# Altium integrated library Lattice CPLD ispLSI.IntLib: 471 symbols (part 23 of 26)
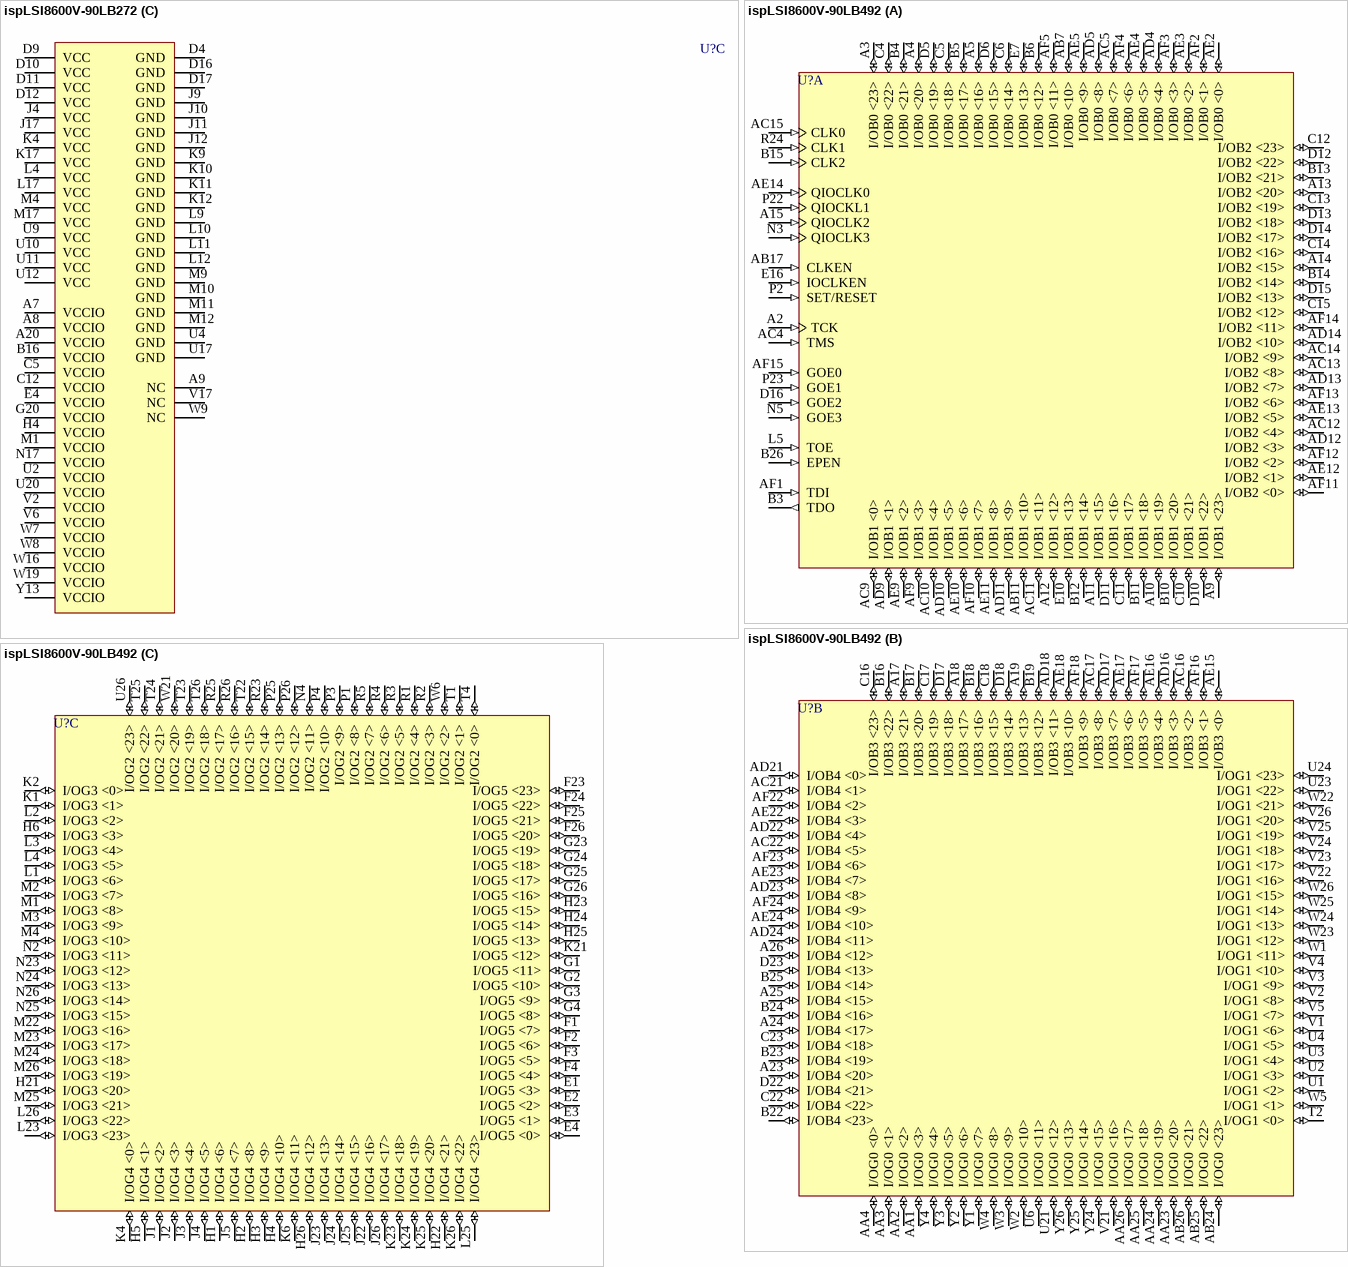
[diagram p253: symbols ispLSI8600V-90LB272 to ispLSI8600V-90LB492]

## ispLSI8600V-90LB272
designator U?
3.3V In-System Programmable SuperBIG High Density PLD
footprint BGA272 (BGA, 272-Leads, Body 27x27mm, Pitch 1.27mm)
3D model 8600V-BGA272 (272-Ball Ball Grid Array (BGA272))
part A pins: A4 TCK (in), A5 I/OB0 <21> (io), A6 I/OB0 <18> (io), A10 I/OB3 <22> (io), A11 I/OB3 <19> (io), A12 I/OB3 <16> (io), A13 I/OB3 <15> (io), A14 I/OB4 <22> (io), A15 I/OB4 <21> (io), A16 I/OB4 <17> (io), A17 I/OB4 <13> (io), B4 I/OB0 <23> (io), B5 I/OB0 <20> (io), B6 I/OB0 <16> (io), B7 I/OB0 <15> (io), B8 I/OB0 <12> (io), B9 IOCLKEN (in), B10 I/OB3 <21> (io), B11 I/OB3 <18> (io), B12 I/OB3 <17> (io), B13 I/OB3 <14> (io), B14 I/OB3 <12> (io), B15 I/OB4 <18> (io), B17 I/OB4 <12> (io), C4 TDO (out), C6 I/OB0 <17> (io), C7 I/OB0 <13> (io), C8 QIOCLK2 (in), C9 GOE2 (in), C10 I/OB3 <23> (io), C11 I/OB3 <20> (io), C13 I/OB4 <23> (io), C14 I/OB4 <20> (io), C15 I/OB4 <16> (io), C16 I/OB4 <14> (io), C17 EPEN (in), D5 I/OB0 <22> (io), D6 I/OB0 <19> (io), D7 I/OB0 <14> (io), D8 CLK2 (in), D13 I/OB3 <13> (io), D14 I/OB4 <19> (io), D15 I/OB4 <15> (io), L3 TOE (in), M19 GOE1 (in), M20 QIOCLK1 (in), N1 GOE3 (in), N2 QIOCLK3 (in), P3 SET/RESET (in), P18 CLK1 (in), R4 I/OG0 <10> (io), R17 I/OG0 <13> (io), T4 I/OG0 <11> (io), T17 I/OG0 <18> (io), U3 I/OG0 <9> (io), U5 TDI (in), U6 I/OB0 <4> (io), U7 I/OB0 <5> (io), U8 I/OB0 <10> (io), U13 I/OB3 <9> (io), U14 I/OB4 <2> (io), U15 I/OB4 <6> (io), U16 I/OB4 <9> (io), U18 I/OG0 <16> (io), U19 I/OG0 <12> (io), V1 I/OG0 <8> (io), V3 I/OG0 <7> (io), V4 I/OG0 <0> (io), V5 I/OB0 <1> (io), V7 I/OB0 <7> (io), V8 I/OB0 <11> (io), V9 CLKEN (in), V10 I/OB3 <0> (io), V11 I/OB3 <4> (io), V12 I/OB3 <7> (io), V13 I/OB3 <10> (io), V14 I/OB4 <1> (io), V15 I/OB4 <5> (io), V16 I/OB4 <8> (io), V18 I/OG0 <17> (io), V19 I/OG0 <15> (io), V20 I/OG0 <14> (io), W1 I/OG0 <6> (io), W2 I/OG0 <5> (io), W3 I/OG0 <3> (io), W4 TMS (in), W5 I/OB0 <2> (io), W6 I/OB0 <6> (io), W10 I/OB3 <1> (io), W11 I/OB3 <3> (io), W12 I/OB3 <6> (io), W13 I/OB3 <8> (io), W14 I/OB4 <0> (io), W15 I/OB4 <4> (io), W17 I/OB4 <10> (io), W18 I/OG0 <22> (io), W20 I/OG0 <19> (io), Y1 I/OG0 <4> (io), Y2 I/OG0 <2> (io), Y3 I/OG0 <1> (io), Y4 I/OB0 <0> (io), Y5 I/OB0 <3> (io), Y6 I/OB0 <8> (io), Y7 I/OB0 <9> (io), Y8 QIOCLK0 (in), Y9 CLK0 (in), Y10 GOE0 (in), Y11 I/OB3 <2> (io), Y12 I/OB3 <5> (io), Y14 I/OB3 <11> (io), Y15 I/OB4 <3> (io), Y16 I/OB4 <7> (io), Y17 I/OB4 <11> (io), Y18 I/OG0 <23> (io), Y19 I/OG0 <21> (io), Y20 I/OG0 <20> (io)
part B pins: A1 I/OG5 <4> (io), A2 I/OG5 <3> (io), A3 I/OG5 <0> (io), A18 I/OG5 <23> (io), A19 I/OG5 <16> (io), B1 I/OG5 <5> (io), B2 I/OG5 <1> (io), B3 I/OG5 <2> (io), B18 I/OG5 <22> (io), B19 I/OG5 <19> (io), B20 I/OG5 <15> (io), C1 I/OG5 <11> (io), C2 I/OG5 <9> (io), C3 I/OG5 <8> (io), C18 I/OG5 <20> (io), C19 I/OG5 <17> (io), C20 I/OG5 <14> (io), D1 I/OG5 <10> (io), D2 I/OG5 <7> (io), D3 I/OG5 <6> (io), D18 I/OG5 <18> (io), D19 I/OG5 <12> (io), D20 I/OG4 <12> (io), E1 I/OG4 <9> (io), E2 I/OG4 <10> (io), E3 I/OG4 <11> (io), E17 I/OG5 <21> (io), E18 I/OG5 <13> (io), E19 I/OG4 <14> (io), E20 I/OG4 <18> (io), F1 I/OG4 <6> (io), F2 I/OG4 <7> (io), F3 I/OG4 <5> (io), F4 I/OG4 <8> (io), F17 I/OG4 <13> (io), F18 I/OG4 <17> (io), F19 I/OG4 <19> (io), F20 I/OG4 <21> (io), G1 I/OG4 <1> (io), G2 I/OG4 <0> (io), G3 I/OG4 <3> (io), G4 I/OG4 <4> (io), G17 I/OG4 <15> (io), G18 I/OG4 <16> (io), G19 I/OG4 <23> (io), H1 I/OG3 <1> (io), H2 I/OG3 <0> (io), H3 I/OG4 <2> (io), H17 I/OG4 <20> (io), H18 I/OG4 <22> (io), H19 I/OG3 <22> (io), H20 I/OG3 <20> (io), J1 I/OG3 <4> (io), J2 I/OG3 <3> (io), J3 I/OG3 <2> (io), J18 I/OG3 <23> (io), J19 I/OG3 <21> (io), J20 I/OG3 <19> (io), K1 I/OG3 <7> (io), K2 I/OG3 <6> (io), K3 I/OG3 <5> (io), K18 I/OG3 <18> (io), K19 I/OG3 <17> (io), K20 I/OG3 <16> (io), L1 I/OG3 <9> (io), L2 I/OG3 <8> (io), L18 I/OG3 <15> (io), L19 I/OG3 <14> (io), L20 I/OG3 <13> (io), M2 I/OG3 <10> (io), M3 I/OG3 <11> (io), M18 I/OG3 <12> (io), N3 I/OG2 <10> (io), N4 I/OG2 <9> (io), N18 I/OG2 <12> (io), N19 I/OG2 <13> (io), N20 I/OG2 <14> (io), P1 I/OG2 <11> (io), P2 I/OG2 <8> (io), P4 I/OG2 <7> (io), P17 I/OG2 <16> (io), P19 I/OG2 <15> (io), P20 I/OG2 <17> (io), R1 I/OG2 <6> (io), R2 I/OG2 <5> (io), R3 I/OG2 <4> (io), R18 I/OG2 <20> (io), R19 I/OG2 <19> (io), R20 I/OG2 <18> (io), T1 I/OG2 <3> (io), T2 I/OG2 <2> (io), T3 I/OG2 <1> (io), T18 I/OG2 <23> (io), T19 I/OG2 <22> (io), T20 I/OG2 <21> (io), U1 I/OG2 <0> (io)
part C pins: A7 VCCIO (power), A8 VCCIO (power), A9 NC, A20 VCCIO (power), B16 VCCIO (power), C5 VCCIO (power), C12 VCCIO (power), D4 GND (power), D9 VCC (power), D10 VCC (power), D11 VCC (power), D12 VCC (power), D16 GND (power), D17 GND (power), E4 VCCIO (power), G20 VCCIO (power), H4 VCCIO (power), J4 VCC (power), J9 GND (power), J10 GND (power), J11 GND (power), J12 GND (power), J17 VCC (power), K4 VCC (power), K9 GND (power), K10 GND (power), K11 GND (power), K12 GND (power), K17 VCC (power), L4 VCC (power), L9 GND (power), L10 GND (power), L11 GND (power), L12 GND (power), L17 VCC (power), M1 VCCIO (power), M4 VCC (power), M9 GND (power), M10 GND (power), M11 GND (power), M12 GND (power), M17 VCC (power), N17 VCCIO (power), U2 VCCIO (power), U4 GND (power), U9 VCC (power), U10 VCC (power), U11 VCC (power), U12 VCC (power), U17 GND (power), U20 VCCIO (power), V2 VCCIO (power), V6 VCCIO (power), V17 NC, W7 VCCIO (power), W8 VCCIO (power), W9 NC, W16 VCCIO (power), W19 VCCIO (power), Y13 VCCIO (power)

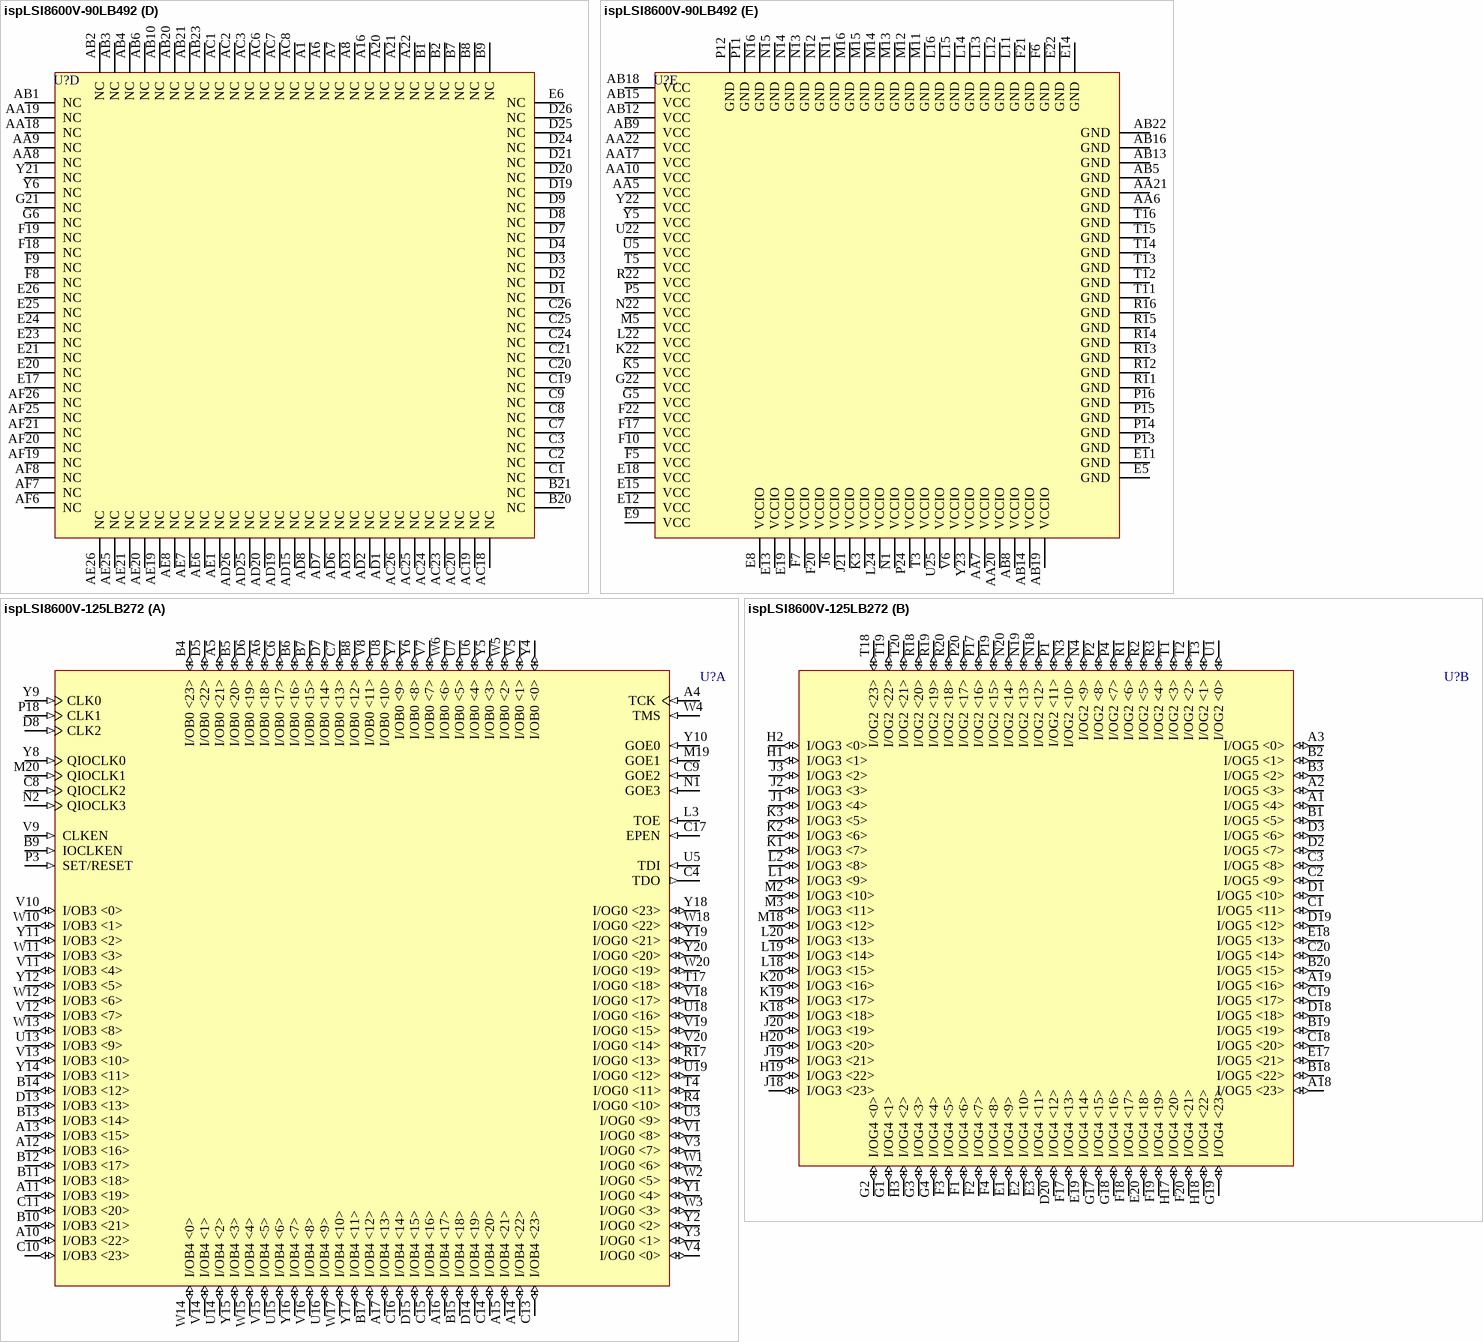
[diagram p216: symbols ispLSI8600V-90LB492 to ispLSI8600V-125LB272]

## ispLSI8600V-90LB492
designator U?
3.3V In-System Programmable SuperBIG High Density PLD
footprint BGA492 (BGA, 492-Leads, Body 35x35mm, Pitch 1.27mm)
3D model 8600V-BGA492 (492-Ball Ball Grid Array (BGA492))
part A pins: A2 TCK (in), A3 I/OB0 <23> (io), A4 I/OB0 <20> (io), A5 I/OB0 <16> (io), A9 I/OB1 <23> (io), A10 I/OB1 <19> (io), A11 I/OB1 <15> (io), A12 I/OB1 <12> (io), A13 I/OB2 <20> (io), A14 I/OB2 <15> (io), A15 QIOCLK2 (in), AB7 I/OB0 <10> (io), AB11 I/OB1 <10> (io), AB17 CLKEN (in), AC4 TMS (in), AC5 I/OB0 <7> (io), AC9 I/OB1 <0> (io), AC10 I/OB1 <4> (io), AC11 I/OB1 <11> (io), AC12 I/OB2 <4> (io), AC13 I/OB2 <8> (io), AC14 I/OB2 <9> (io), AC15 CLK0 (in), AD4 I/OB0 <4> (io), AD5 I/OB0 <8> (io), AD9 I/OB1 <1> (io), AD10 I/OB1 <5> (io), AD11 I/OB1 <9> (io), AD12 I/OB2 <3> (io), AD13 I/OB2 <7> (io), AD14 I/OB2 <10> (io), AE2 I/OB0 <0> (io), AE3 I/OB0 <2> (io), AE4 I/OB0 <5> (io), AE5 I/OB0 <9> (io), AE9 I/OB1 <2> (io), AE10 I/OB1 <6> (io), AE11 I/OB1 <8> (io), AE12 I/OB2 <1> (io), AE13 I/OB2 <5> (io), AE14 QIOCLK0 (in), AF1 TDI (in), AF2 I/OB0 <1> (io), AF3 I/OB0 <3> (io), AF4 I/OB0 <6> (io), AF5 I/OB0 <11> (io), AF9 I/OB1 <3> (io), AF10 I/OB1 <7> (io), AF11 I/OB2 <0> (io), AF12 I/OB2 <2> (io), AF13 I/OB2 <6> (io), AF14 I/OB2 <11> (io), AF15 GOE0 (in), B3 TDO (out), B4 I/OB0 <21> (io), B5 I/OB0 <17> (io), B6 I/OB0 <12> (io), B10 I/OB1 <20> (io), B11 I/OB1 <18> (io), B12 I/OB1 <14> (io), B13 I/OB2 <21> (io), B14 I/OB2 <14> (io), B15 CLK2 (in), B26 EPEN (in), C4 I/OB0 <22> (io), C5 I/OB0 <18> (io), C6 I/OB0 <14> (io), C10 I/OB1 <21> (io), C11 I/OB1 <17> (io), C12 I/OB2 <23> (io), C13 I/OB2 <19> (io), C14 I/OB2 <16> (io), C15 I/OB2 <12> (io), D5 I/OB0 <19> (io), D6 I/OB0 <15> (io), D10 I/OB1 <22> (io), D11 I/OB1 <16> (io), D12 I/OB2 <22> (io), D13 I/OB2 <18> (io), D14 I/OB2 <17> (io), D15 I/OB2 <13> (io), D16 GOE2 (in), E7 I/OB0 <13> (io), E10 I/OB1 <13> (io), E16 IOCLKEN (in), L5 TOE (in), N3 QIOCLK3 (in), N5 GOE3 (in), P2 SET/RESET (in), P22 QIOCKL1 (in), P23 GOE1 (in), R24 CLK1 (in)
part B pins: A17 I/OB3 <21> (io), A18 I/OB3 <17> (io), A19 I/OB3 <13> (io), A23 I/OB4 <20> (io), A24 I/OB4 <17> (io), A25 I/OB4 <15> (io), A26 I/OB4 <12> (io), AA1 I/OG0 <3> (io), AA2 I/OG0 <2> (io), AA3 I/OG0 <1> (io), AA4 I/OG0 <0> (io), AA23 I/OG0 <20> (io), AA24 I/OG0 <19> (io), AA25 I/OG0 <18> (io), AA26 I/OG0 <17> (io), AB24 I/OG0 <23> (io), AB25 I/OG0 <22> (io), AB26 I/OG0 <21> (io), AC16 I/OB3 <2> (io), AC17 I/OB3 <8> (io), AC21 I/OB4 <1> (io), AC22 I/OB4 <5> (io), AD16 I/OB3 <3> (io), AD17 I/OB3 <7> (io), AD18 I/OB3 <11> (io), AD21 I/OB4 <0> (io), AD22 I/OB4 <4> (io), AD23 I/OB4 <8> (io), AD24 I/OB4 <11> (io), AE15 I/OB3 <0> (io), AE16 I/OB3 <4> (io), AE17 I/OB3 <6> (io), AE18 I/OB3 <10> (io), AE22 I/OB4 <3> (io), AE23 I/OB4 <7> (io), AE24 I/OB4 <10> (io), AF16 I/OB3 <1> (io), AF17 I/OB3 <5> (io), AF18 I/OB3 <9> (io), AF22 I/OB4 <2> (io), AF23 I/OB4 <6> (io), AF24 I/OB4 <9> (io), B16 I/OB3 <22> (io), B17 I/OB3 <20> (io), B18 I/OB3 <16> (io), B19 I/OB3 <12> (io), B22 I/OB4 <23> (io), B23 I/OB4 <19> (io), B24 I/OB4 <16> (io), B25 I/OB4 <14> (io), C16 I/OB3 <23> (io), C17 I/OB3 <19> (io), C18 I/OB3 <15> (io), C22 I/OB4 <22> (io), C23 I/OB4 <18> (io), D17 I/OB3 <18> (io), D18 I/OB3 <14> (io), D22 I/OB4 <21> (io), D23 I/OB4 <13> (io), T2 I/OG1 <0> (io), U1 I/OG1 <2> (io), U2 I/OG1 <3> (io), U3 I/OG1 <4> (io), U4 I/OG1 <5> (io), U6 I/OG0 <11> (io), U21 I/OG0 <12> (io), U23 I/OG1 <22> (io), U24 I/OG1 <23> (io), V1 I/OG1 <6> (io), V2 I/OG1 <8> (io), V3 I/OG1 <9> (io), V4 I/OG1 <10> (io), V5 I/OG1 <7> (io), V21 I/OG0 <16> (io), V22 I/OG1 <16> (io), V23 I/OG1 <17> (io), V24 I/OG1 <18> (io), V25 I/OG1 <19> (io), V26 I/OG1 <20> (io), W1 I/OG1 <11> (io), W2 I/OG0 <10> (io), W3 I/OG0 <9> (io), W4 I/OG0 <8> (io), W5 I/OG1 <1> (io), W22 I/OG1 <21> (io), W23 I/OG1 <12> (io), W24 I/OG1 <13> (io), W25 I/OG1 <14> (io), W26 I/OG1 <15> (io), Y1 I/OG0 <7> (io), Y2 I/OG0 <6> (io), Y3 I/OG0 <5> (io), Y4 I/OG0 <4> (io), Y24 I/OG0 <15> (io), Y25 I/OG0 <14> (io), Y26 I/OG0 <13> (io)
part C pins: E1 I/OG5 <3> (io), E2 I/OG5 <2> (io), E3 I/OG5 <1> (io), E4 I/OG5 <0> (io), F1 I/OG5 <7> (io), F2 I/OG5 <6> (io), F3 I/OG5 <5> (io), F4 I/OG5 <4> (io), F23 I/OG5 <23> (io), F24 I/OG5 <22> (io), F25 I/OG5 <21> (io), F26 I/OG5 <20> (io), G1 I/OG5 <11> (io), G2 I/OG5 <10> (io), G3 I/OG5 <9> (io), G4 I/OG5 <8> (io), G23 I/OG5 <19> (io), G24 I/OG5 <18> (io), G25 I/OG5 <17> (io), G26 I/OG5 <16> (io), H1 I/OG4 <6> (io), H2 I/OG4 <8> (io), H3 I/OG4 <9> (io), H4 I/OG4 <10> (io), H5 I/OG4 <1> (io), H6 I/OG3 <3> (io), H21 I/OG3 <20> (io), H22 I/OG4 <21> (io), H23 I/OG5 <15> (io), H24 I/OG5 <14> (io), H25 I/OG5 <13> (io), H26 I/OG4 <12> (io), J1 I/OG4 <2> (io), J2 I/OG4 <3> (io), J3 I/OG4 <4> (io), J4 I/OG4 <5> (io), J5 I/OG4 <7> (io), J22 I/OG4 <16> (io), J23 I/OG4 <13> (io), J24 I/OG4 <14> (io), J25 I/OG4 <15> (io), J26 I/OG4 <17> (io), K1 I/OG3 <1> (io), K2 I/OG3 <0> (io), K4 I/OG4 <0> (io), K6 I/OG4 <11> (io), K21 I/OG5 <12> (io), K23 I/OG4 <18> (io), K24 I/OG4 <19> (io), K25 I/OG4 <20> (io), K26 I/OG4 <22> (io), L1 I/OG3 <6> (io), L2 I/OG3 <2> (io), L3 I/OG3 <4> (io), L4 I/OG3 <5> (io), L23 I/OG3 <23> (io), L25 I/OG4 <23> (io), L26 I/OG3 <22> (io), M1 I/OG3 <8> (io), M2 I/OG3 <7> (io), M3 I/OG3 <9> (io), M4 I/OG3 <10> (io), M22 I/OG3 <16> (io), M23 I/OG3 <17> (io), M24 I/OG3 <18> (io), M25 I/OG3 <21> (io), M26 I/OG3 <19> (io), N2 I/OG3 <11> (io), N4 I/OG2 <11> (io), N23 I/OG3 <12> (io), N24 I/OG3 <13> (io), N25 I/OG3 <15> (io), N26 I/OG3 <14> (io), P1 I/OG2 <8> (io), P3 I/OG2 <9> (io), P4 I/OG2 <10> (io), P25 I/OG2 <13> (io), P26 I/OG2 <12> (io), R1 I/OG2 <4> (io), R2 I/OG2 <3> (io), R3 I/OG2 <5> (io), R4 I/OG2 <6> (io), R5 I/OG2 <7> (io), R23 I/OG2 <14> (io), R25 I/OG2 <17> (io), R26 I/OG2 <16> (io), T1 I/OG2 <1> (io), T4 I/OG2 <0> (io), T22 I/OG2 <15> (io), T23 I/OG2 <19> (io), T24 I/OG2 <21> (io), T25 I/OG2 <22> (io), T26 I/OG2 <18> (io), U26 I/OG2 <23> (io), W6 I/OG2 <2> (io), W21 I/OG2 <20> (io)
part D pins: A1 NC, A6 NC, A7 NC, A8 NC, A16 NC, A20 NC, A21 NC, A22 NC, AA8 NC, AA9 NC, AA18 NC, AA19 NC, AB1 NC, AB2 NC, AB3 NC, AB4 NC, AB6 NC, AB10 NC, AB20 NC, AB21 NC, AB23 NC, AC1 NC, AC2 NC, AC3 NC, AC6 NC, AC7 NC, AC8 NC, AC18 NC, AC19 NC, AC20 NC, AC23 NC, AC24 NC, AC25 NC, AC26 NC, AD1 NC, AD2 NC, AD3 NC, AD6 NC, AD7 NC, AD8 NC, AD15 NC, AD19 NC, AD20 NC, AD25 NC, AD26 NC, AE1 NC, AE6 NC, AE7 NC, AE8 NC, AE19 NC, AE20 NC, AE21 NC, AE25 NC, AE26 NC, AF6 NC, AF7 NC, AF8 NC, AF19 NC, AF20 NC, AF21 NC, AF25 NC, AF26 NC, B1 NC, B2 NC, B7 NC, B8 NC, B9 NC, B20 NC, B21 NC, C1 NC, C2 NC, C3 NC, C7 NC, C8 NC, C9 NC, C19 NC, C20 NC, C21 NC, C24 NC, C25 NC, C26 NC, D1 NC, D2 NC, D3 NC, D4 NC, D7 NC, D8 NC, D9 NC, D19 NC, D20 NC, D21 NC, D24 NC, D25 NC, D26 NC, E6 NC, E17 NC, E20 NC, E21 NC, E23 NC, E24 NC, E25 NC, E26 NC, F8 NC, F9 NC, F18 NC, F19 NC, G6 NC, G21 NC, Y6 NC, Y21 NC
part E pins: AA5 VCC (power), AA6 GND (power), AA7 VCCIO (power), AA10 VCC (power), AA17 VCC (power), AA20 VCCIO (power), AA21 GND (power), AA22 VCC (power), AB5 GND (power), AB8 VCCIO (power), AB9 VCC (power), AB12 VCC (power), AB13 GND (power), AB14 VCCIO (power), AB15 VCC (power), AB16 GND (power), AB18 VCC (power), AB19 VCCIO (power), AB22 GND (power), E5 GND (power), E8 VCCIO (power), E9 VCC (power), E11 GND (power), E12 VCC (power), E13 VCCIO (power), E14 GND (power), E15 VCC (power), E18 VCC (power), E19 VCCIO (power), E22 GND (power), F5 VCC (power), F6 GND (power), F7 VCCIO (power), F10 VCC (power), F17 VCC (power), F20 VCCIO (power), F21 GND (power), F22 VCC (power), G5 VCC (power), G22 VCC (power), J6 VCCIO (power), J21 VCCIO (power), K3 VCCIO (power), K5 VCC (power), K22 VCC (power), L11 GND (power), L12 GND (power), L13 GND (power), L14 GND (power), L15 GND (power), L16 GND (power), L22 VCC (power), L24 VCCIO (power), M5 VCC (power), M11 GND (power), M12 GND (power), M13 GND (power), M14 GND (power), M15 GND (power), M16 GND (power), N1 VCCIO (power), N11 GND (power), N12 GND (power), N13 GND (power), N14 GND (power), N15 GND (power), N16 GND (power), N22 VCC (power), P5 VCC (power), P11 GND (power), P12 GND (power), P13 GND (power), P14 GND (power), P15 GND (power), P16 GND (power), P24 VCCIO (power), R11 GND (power), R12 GND (power), R13 GND (power), R14 GND (power), R15 GND (power), R16 GND (power), R22 VCC (power), T3 VCCIO (power), T5 VCC (power), T11 GND (power), T12 GND (power), T13 GND (power), T14 GND (power), T15 GND (power), T16 GND (power), U5 VCC (power), U22 VCC (power), U25 VCCIO (power), V6 VCCIO (power), Y5 VCC (power), Y22 VCC (power), Y23 VCCIO (power)

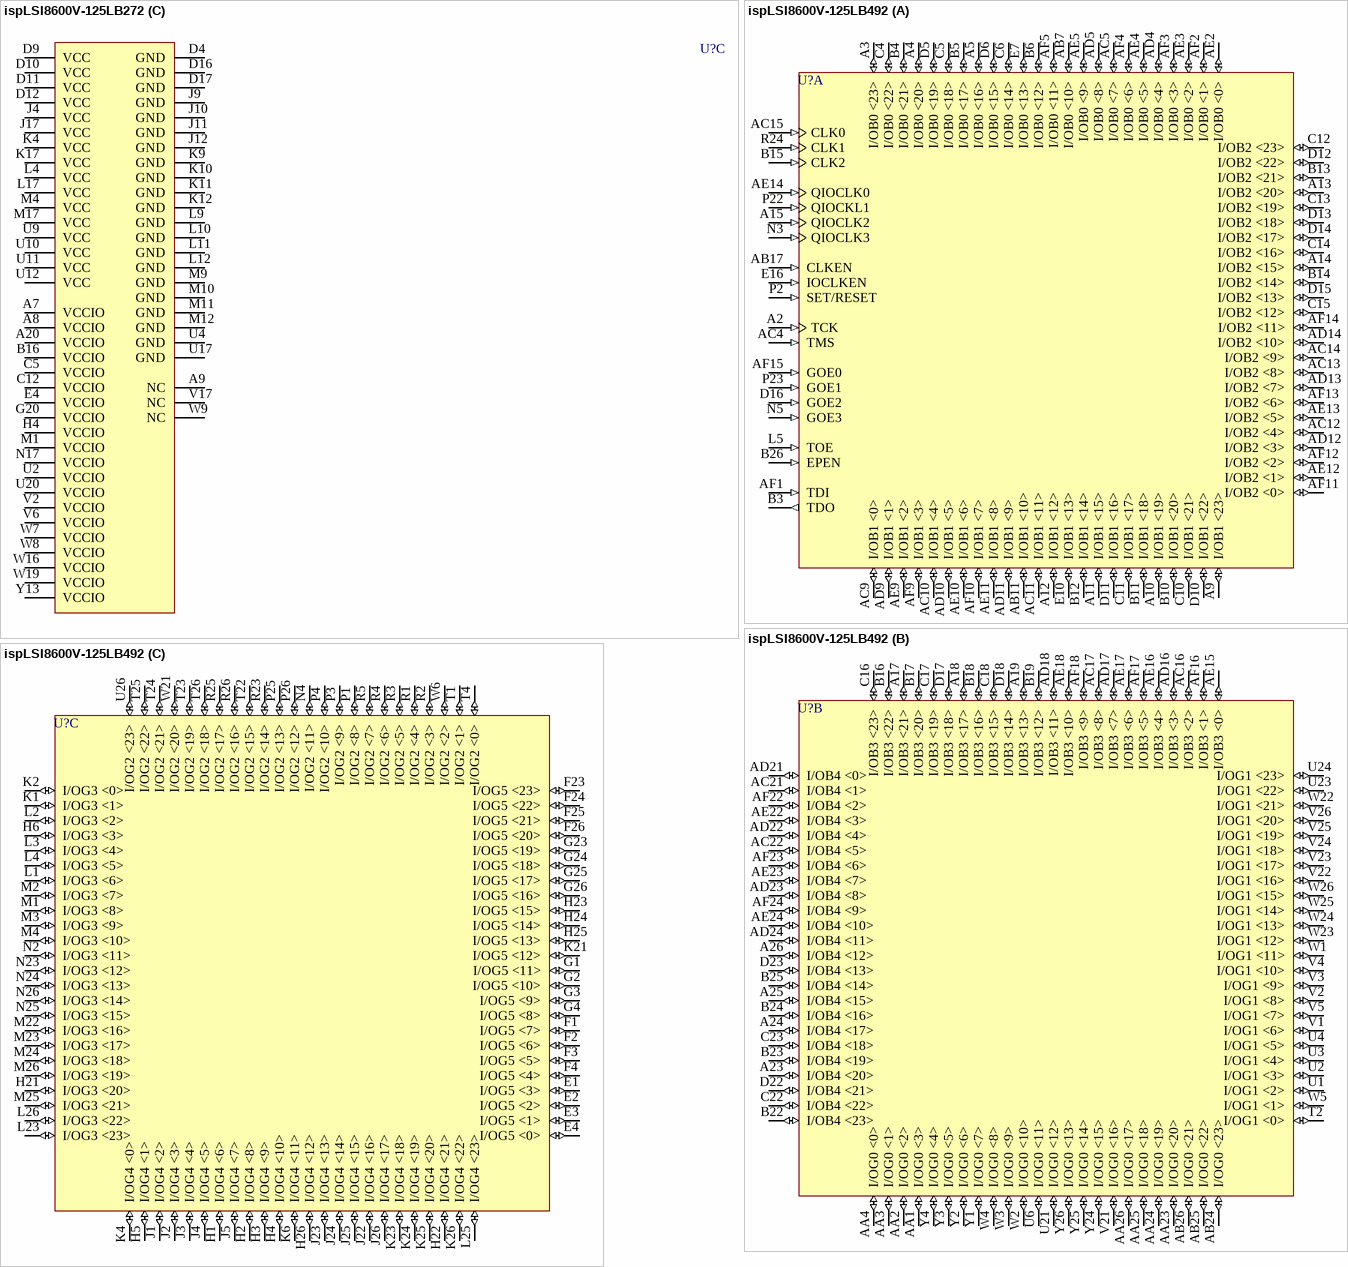
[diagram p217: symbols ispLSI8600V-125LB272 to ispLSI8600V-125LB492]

## ispLSI8600V-125LB272
designator U?
3.3V In-System Programmable SuperBIG High Density PLD
footprint BGA272 (BGA, 272-Leads, Body 27x27mm, Pitch 1.27mm)
3D model 8600V-BGA272 (272-Ball Ball Grid Array (BGA272))
part A pins: A4 TCK (in), A5 I/OB0 <21> (io), A6 I/OB0 <18> (io), A10 I/OB3 <22> (io), A11 I/OB3 <19> (io), A12 I/OB3 <16> (io), A13 I/OB3 <15> (io), A14 I/OB4 <22> (io), A15 I/OB4 <21> (io), A16 I/OB4 <17> (io), A17 I/OB4 <13> (io), B4 I/OB0 <23> (io), B5 I/OB0 <20> (io), B6 I/OB0 <16> (io), B7 I/OB0 <15> (io), B8 I/OB0 <12> (io), B9 IOCLKEN (in), B10 I/OB3 <21> (io), B11 I/OB3 <18> (io), B12 I/OB3 <17> (io), B13 I/OB3 <14> (io), B14 I/OB3 <12> (io), B15 I/OB4 <18> (io), B17 I/OB4 <12> (io), C4 TDO (out), C6 I/OB0 <17> (io), C7 I/OB0 <13> (io), C8 QIOCLK2 (in), C9 GOE2 (in), C10 I/OB3 <23> (io), C11 I/OB3 <20> (io), C13 I/OB4 <23> (io), C14 I/OB4 <20> (io), C15 I/OB4 <16> (io), C16 I/OB4 <14> (io), C17 EPEN (in), D5 I/OB0 <22> (io), D6 I/OB0 <19> (io), D7 I/OB0 <14> (io), D8 CLK2 (in), D13 I/OB3 <13> (io), D14 I/OB4 <19> (io), D15 I/OB4 <15> (io), L3 TOE (in), M19 GOE1 (in), M20 QIOCLK1 (in), N1 GOE3 (in), N2 QIOCLK3 (in), P3 SET/RESET (in), P18 CLK1 (in), R4 I/OG0 <10> (io), R17 I/OG0 <13> (io), T4 I/OG0 <11> (io), T17 I/OG0 <18> (io), U3 I/OG0 <9> (io), U5 TDI (in), U6 I/OB0 <4> (io), U7 I/OB0 <5> (io), U8 I/OB0 <10> (io), U13 I/OB3 <9> (io), U14 I/OB4 <2> (io), U15 I/OB4 <6> (io), U16 I/OB4 <9> (io), U18 I/OG0 <16> (io), U19 I/OG0 <12> (io), V1 I/OG0 <8> (io), V3 I/OG0 <7> (io), V4 I/OG0 <0> (io), V5 I/OB0 <1> (io), V7 I/OB0 <7> (io), V8 I/OB0 <11> (io), V9 CLKEN (in), V10 I/OB3 <0> (io), V11 I/OB3 <4> (io), V12 I/OB3 <7> (io), V13 I/OB3 <10> (io), V14 I/OB4 <1> (io), V15 I/OB4 <5> (io), V16 I/OB4 <8> (io), V18 I/OG0 <17> (io), V19 I/OG0 <15> (io), V20 I/OG0 <14> (io), W1 I/OG0 <6> (io), W2 I/OG0 <5> (io), W3 I/OG0 <3> (io), W4 TMS (in), W5 I/OB0 <2> (io), W6 I/OB0 <6> (io), W10 I/OB3 <1> (io), W11 I/OB3 <3> (io), W12 I/OB3 <6> (io), W13 I/OB3 <8> (io), W14 I/OB4 <0> (io), W15 I/OB4 <4> (io), W17 I/OB4 <10> (io), W18 I/OG0 <22> (io), W20 I/OG0 <19> (io), Y1 I/OG0 <4> (io), Y2 I/OG0 <2> (io), Y3 I/OG0 <1> (io), Y4 I/OB0 <0> (io), Y5 I/OB0 <3> (io), Y6 I/OB0 <8> (io), Y7 I/OB0 <9> (io), Y8 QIOCLK0 (in), Y9 CLK0 (in), Y10 GOE0 (in), Y11 I/OB3 <2> (io), Y12 I/OB3 <5> (io), Y14 I/OB3 <11> (io), Y15 I/OB4 <3> (io), Y16 I/OB4 <7> (io), Y17 I/OB4 <11> (io), Y18 I/OG0 <23> (io), Y19 I/OG0 <21> (io), Y20 I/OG0 <20> (io)
part B pins: A1 I/OG5 <4> (io), A2 I/OG5 <3> (io), A3 I/OG5 <0> (io), A18 I/OG5 <23> (io), A19 I/OG5 <16> (io), B1 I/OG5 <5> (io), B2 I/OG5 <1> (io), B3 I/OG5 <2> (io), B18 I/OG5 <22> (io), B19 I/OG5 <19> (io), B20 I/OG5 <15> (io), C1 I/OG5 <11> (io), C2 I/OG5 <9> (io), C3 I/OG5 <8> (io), C18 I/OG5 <20> (io), C19 I/OG5 <17> (io), C20 I/OG5 <14> (io), D1 I/OG5 <10> (io), D2 I/OG5 <7> (io), D3 I/OG5 <6> (io), D18 I/OG5 <18> (io), D19 I/OG5 <12> (io), D20 I/OG4 <12> (io), E1 I/OG4 <9> (io), E2 I/OG4 <10> (io), E3 I/OG4 <11> (io), E17 I/OG5 <21> (io), E18 I/OG5 <13> (io), E19 I/OG4 <14> (io), E20 I/OG4 <18> (io), F1 I/OG4 <6> (io), F2 I/OG4 <7> (io), F3 I/OG4 <5> (io), F4 I/OG4 <8> (io), F17 I/OG4 <13> (io), F18 I/OG4 <17> (io), F19 I/OG4 <19> (io), F20 I/OG4 <21> (io), G1 I/OG4 <1> (io), G2 I/OG4 <0> (io), G3 I/OG4 <3> (io), G4 I/OG4 <4> (io), G17 I/OG4 <15> (io), G18 I/OG4 <16> (io), G19 I/OG4 <23> (io), H1 I/OG3 <1> (io), H2 I/OG3 <0> (io), H3 I/OG4 <2> (io), H17 I/OG4 <20> (io), H18 I/OG4 <22> (io), H19 I/OG3 <22> (io), H20 I/OG3 <20> (io), J1 I/OG3 <4> (io), J2 I/OG3 <3> (io), J3 I/OG3 <2> (io), J18 I/OG3 <23> (io), J19 I/OG3 <21> (io), J20 I/OG3 <19> (io), K1 I/OG3 <7> (io), K2 I/OG3 <6> (io), K3 I/OG3 <5> (io), K18 I/OG3 <18> (io), K19 I/OG3 <17> (io), K20 I/OG3 <16> (io), L1 I/OG3 <9> (io), L2 I/OG3 <8> (io), L18 I/OG3 <15> (io), L19 I/OG3 <14> (io), L20 I/OG3 <13> (io), M2 I/OG3 <10> (io), M3 I/OG3 <11> (io), M18 I/OG3 <12> (io), N3 I/OG2 <10> (io), N4 I/OG2 <9> (io), N18 I/OG2 <12> (io), N19 I/OG2 <13> (io), N20 I/OG2 <14> (io), P1 I/OG2 <11> (io), P2 I/OG2 <8> (io), P4 I/OG2 <7> (io), P17 I/OG2 <16> (io), P19 I/OG2 <15> (io), P20 I/OG2 <17> (io), R1 I/OG2 <6> (io), R2 I/OG2 <5> (io), R3 I/OG2 <4> (io), R18 I/OG2 <20> (io), R19 I/OG2 <19> (io), R20 I/OG2 <18> (io), T1 I/OG2 <3> (io), T2 I/OG2 <2> (io), T3 I/OG2 <1> (io), T18 I/OG2 <23> (io), T19 I/OG2 <22> (io), T20 I/OG2 <21> (io), U1 I/OG2 <0> (io)
part C pins: A7 VCCIO (power), A8 VCCIO (power), A9 NC, A20 VCCIO (power), B16 VCCIO (power), C5 VCCIO (power), C12 VCCIO (power), D4 GND (power), D9 VCC (power), D10 VCC (power), D11 VCC (power), D12 VCC (power), D16 GND (power), D17 GND (power), E4 VCCIO (power), G20 VCCIO (power), H4 VCCIO (power), J4 VCC (power), J9 GND (power), J10 GND (power), J11 GND (power), J12 GND (power), J17 VCC (power), K4 VCC (power), K9 GND (power), K10 GND (power), K11 GND (power), K12 GND (power), K17 VCC (power), L4 VCC (power), L9 GND (power), L10 GND (power), L11 GND (power), L12 GND (power), L17 VCC (power), M1 VCCIO (power), M4 VCC (power), M9 GND (power), M10 GND (power), M11 GND (power), M12 GND (power), M17 VCC (power), N17 VCCIO (power), U2 VCCIO (power), U4 GND (power), U9 VCC (power), U10 VCC (power), U11 VCC (power), U12 VCC (power), U17 GND (power), U20 VCCIO (power), V2 VCCIO (power), V6 VCCIO (power), V17 NC, W7 VCCIO (power), W8 VCCIO (power), W9 NC, W16 VCCIO (power), W19 VCCIO (power), Y13 VCCIO (power)

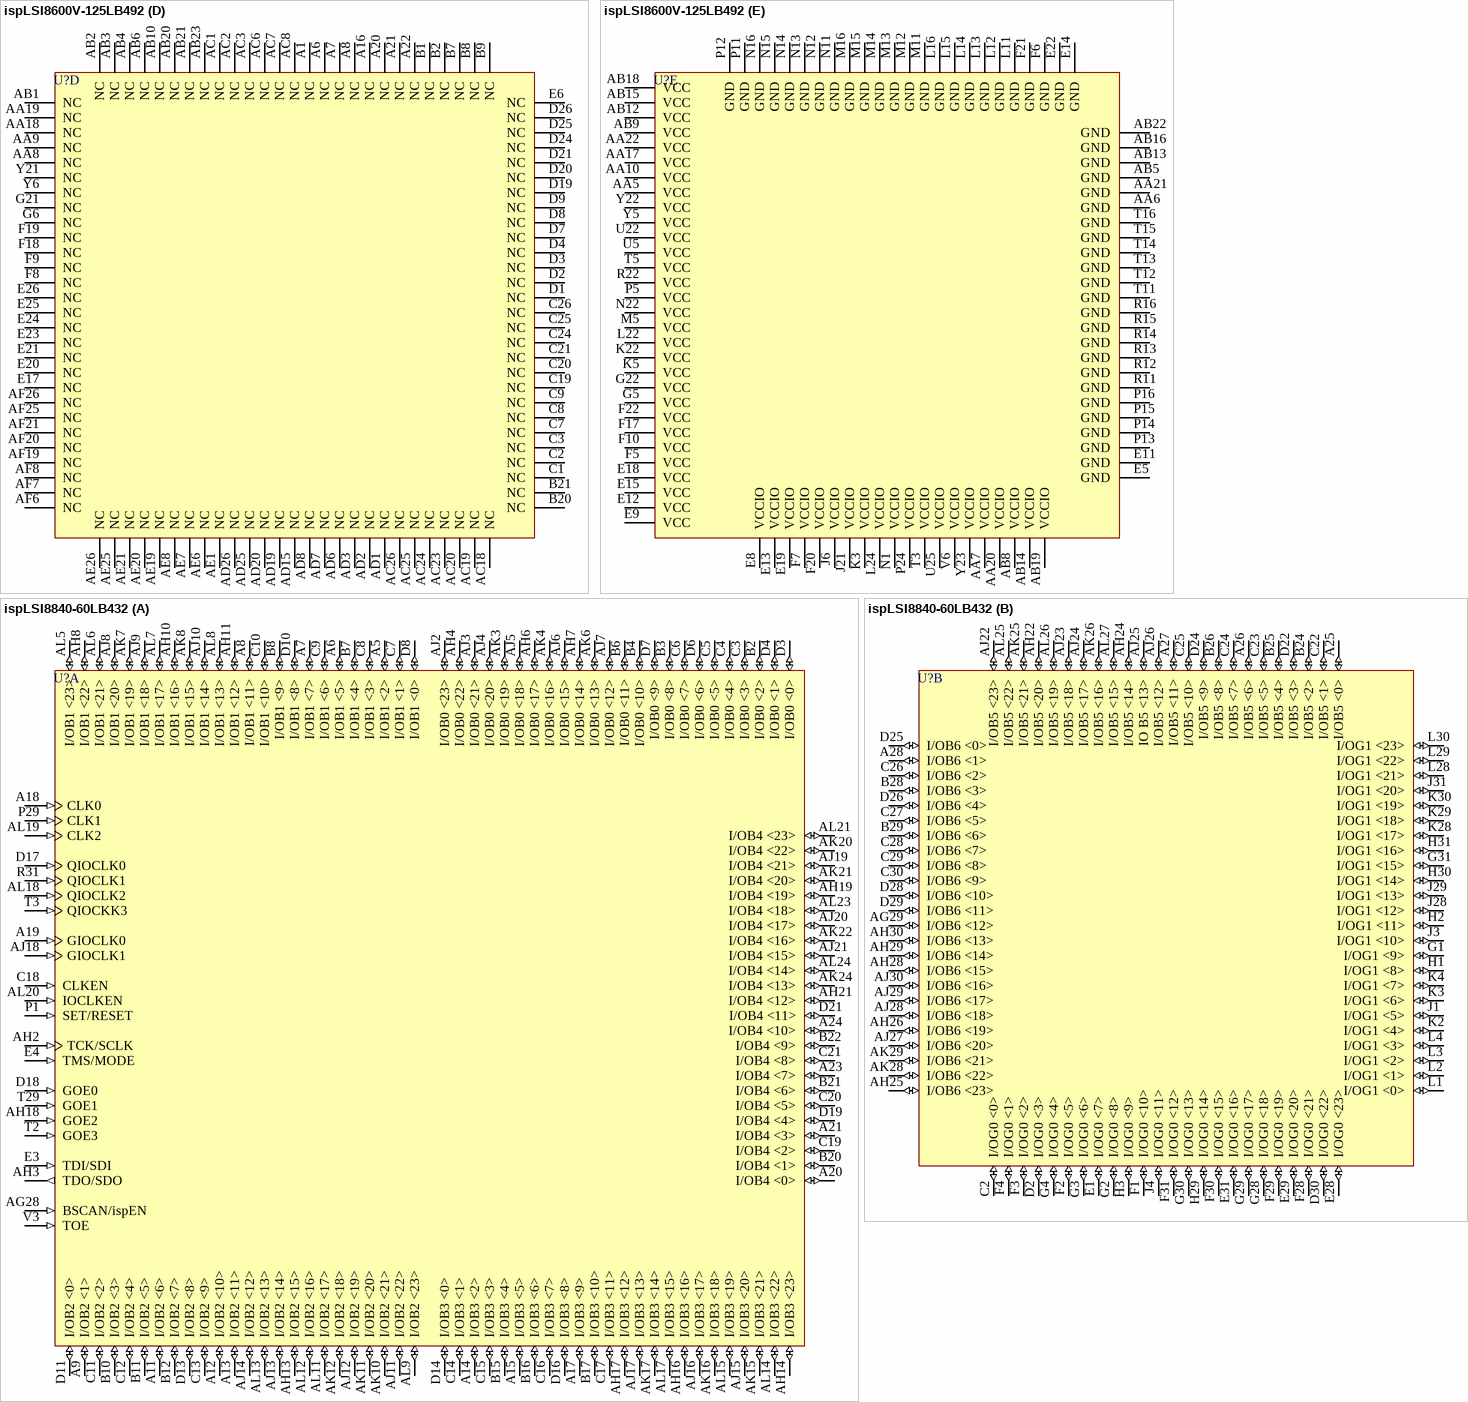
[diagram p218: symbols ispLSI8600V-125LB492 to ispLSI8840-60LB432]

## ispLSI8600V-125LB492
designator U?
3.3V In-System Programmable SuperBIG High Density PLD
footprint BGA492 (BGA, 492-Leads, Body 35x35mm, Pitch 1.27mm)
3D model 8600V-BGA492 (492-Ball Ball Grid Array (BGA492))
part A pins: A2 TCK (in), A3 I/OB0 <23> (io), A4 I/OB0 <20> (io), A5 I/OB0 <16> (io), A9 I/OB1 <23> (io), A10 I/OB1 <19> (io), A11 I/OB1 <15> (io), A12 I/OB1 <12> (io), A13 I/OB2 <20> (io), A14 I/OB2 <15> (io), A15 QIOCLK2 (in), AB7 I/OB0 <10> (io), AB11 I/OB1 <10> (io), AB17 CLKEN (in), AC4 TMS (in), AC5 I/OB0 <7> (io), AC9 I/OB1 <0> (io), AC10 I/OB1 <4> (io), AC11 I/OB1 <11> (io), AC12 I/OB2 <4> (io), AC13 I/OB2 <8> (io), AC14 I/OB2 <9> (io), AC15 CLK0 (in), AD4 I/OB0 <4> (io), AD5 I/OB0 <8> (io), AD9 I/OB1 <1> (io), AD10 I/OB1 <5> (io), AD11 I/OB1 <9> (io), AD12 I/OB2 <3> (io), AD13 I/OB2 <7> (io), AD14 I/OB2 <10> (io), AE2 I/OB0 <0> (io), AE3 I/OB0 <2> (io), AE4 I/OB0 <5> (io), AE5 I/OB0 <9> (io), AE9 I/OB1 <2> (io), AE10 I/OB1 <6> (io), AE11 I/OB1 <8> (io), AE12 I/OB2 <1> (io), AE13 I/OB2 <5> (io), AE14 QIOCLK0 (in), AF1 TDI (in), AF2 I/OB0 <1> (io), AF3 I/OB0 <3> (io), AF4 I/OB0 <6> (io), AF5 I/OB0 <11> (io), AF9 I/OB1 <3> (io), AF10 I/OB1 <7> (io), AF11 I/OB2 <0> (io), AF12 I/OB2 <2> (io), AF13 I/OB2 <6> (io), AF14 I/OB2 <11> (io), AF15 GOE0 (in), B3 TDO (out), B4 I/OB0 <21> (io), B5 I/OB0 <17> (io), B6 I/OB0 <12> (io), B10 I/OB1 <20> (io), B11 I/OB1 <18> (io), B12 I/OB1 <14> (io), B13 I/OB2 <21> (io), B14 I/OB2 <14> (io), B15 CLK2 (in), B26 EPEN (in), C4 I/OB0 <22> (io), C5 I/OB0 <18> (io), C6 I/OB0 <14> (io), C10 I/OB1 <21> (io), C11 I/OB1 <17> (io), C12 I/OB2 <23> (io), C13 I/OB2 <19> (io), C14 I/OB2 <16> (io), C15 I/OB2 <12> (io), D5 I/OB0 <19> (io), D6 I/OB0 <15> (io), D10 I/OB1 <22> (io), D11 I/OB1 <16> (io), D12 I/OB2 <22> (io), D13 I/OB2 <18> (io), D14 I/OB2 <17> (io), D15 I/OB2 <13> (io), D16 GOE2 (in), E7 I/OB0 <13> (io), E10 I/OB1 <13> (io), E16 IOCLKEN (in), L5 TOE (in), N3 QIOCLK3 (in), N5 GOE3 (in), P2 SET/RESET (in), P22 QIOCKL1 (in), P23 GOE1 (in), R24 CLK1 (in)
part B pins: A17 I/OB3 <21> (io), A18 I/OB3 <17> (io), A19 I/OB3 <13> (io), A23 I/OB4 <20> (io), A24 I/OB4 <17> (io), A25 I/OB4 <15> (io), A26 I/OB4 <12> (io), AA1 I/OG0 <3> (io), AA2 I/OG0 <2> (io), AA3 I/OG0 <1> (io), AA4 I/OG0 <0> (io), AA23 I/OG0 <20> (io), AA24 I/OG0 <19> (io), AA25 I/OG0 <18> (io), AA26 I/OG0 <17> (io), AB24 I/OG0 <23> (io), AB25 I/OG0 <22> (io), AB26 I/OG0 <21> (io), AC16 I/OB3 <2> (io), AC17 I/OB3 <8> (io), AC21 I/OB4 <1> (io), AC22 I/OB4 <5> (io), AD16 I/OB3 <3> (io), AD17 I/OB3 <7> (io), AD18 I/OB3 <11> (io), AD21 I/OB4 <0> (io), AD22 I/OB4 <4> (io), AD23 I/OB4 <8> (io), AD24 I/OB4 <11> (io), AE15 I/OB3 <0> (io), AE16 I/OB3 <4> (io), AE17 I/OB3 <6> (io), AE18 I/OB3 <10> (io), AE22 I/OB4 <3> (io), AE23 I/OB4 <7> (io), AE24 I/OB4 <10> (io), AF16 I/OB3 <1> (io), AF17 I/OB3 <5> (io), AF18 I/OB3 <9> (io), AF22 I/OB4 <2> (io), AF23 I/OB4 <6> (io), AF24 I/OB4 <9> (io), B16 I/OB3 <22> (io), B17 I/OB3 <20> (io), B18 I/OB3 <16> (io), B19 I/OB3 <12> (io), B22 I/OB4 <23> (io), B23 I/OB4 <19> (io), B24 I/OB4 <16> (io), B25 I/OB4 <14> (io), C16 I/OB3 <23> (io), C17 I/OB3 <19> (io), C18 I/OB3 <15> (io), C22 I/OB4 <22> (io), C23 I/OB4 <18> (io), D17 I/OB3 <18> (io), D18 I/OB3 <14> (io), D22 I/OB4 <21> (io), D23 I/OB4 <13> (io), T2 I/OG1 <0> (io), U1 I/OG1 <2> (io), U2 I/OG1 <3> (io), U3 I/OG1 <4> (io), U4 I/OG1 <5> (io), U6 I/OG0 <11> (io), U21 I/OG0 <12> (io), U23 I/OG1 <22> (io), U24 I/OG1 <23> (io), V1 I/OG1 <6> (io), V2 I/OG1 <8> (io), V3 I/OG1 <9> (io), V4 I/OG1 <10> (io), V5 I/OG1 <7> (io), V21 I/OG0 <16> (io), V22 I/OG1 <16> (io), V23 I/OG1 <17> (io), V24 I/OG1 <18> (io), V25 I/OG1 <19> (io), V26 I/OG1 <20> (io), W1 I/OG1 <11> (io), W2 I/OG0 <10> (io), W3 I/OG0 <9> (io), W4 I/OG0 <8> (io), W5 I/OG1 <1> (io), W22 I/OG1 <21> (io), W23 I/OG1 <12> (io), W24 I/OG1 <13> (io), W25 I/OG1 <14> (io), W26 I/OG1 <15> (io), Y1 I/OG0 <7> (io), Y2 I/OG0 <6> (io), Y3 I/OG0 <5> (io), Y4 I/OG0 <4> (io), Y24 I/OG0 <15> (io), Y25 I/OG0 <14> (io), Y26 I/OG0 <13> (io)
part C pins: E1 I/OG5 <3> (io), E2 I/OG5 <2> (io), E3 I/OG5 <1> (io), E4 I/OG5 <0> (io), F1 I/OG5 <7> (io), F2 I/OG5 <6> (io), F3 I/OG5 <5> (io), F4 I/OG5 <4> (io), F23 I/OG5 <23> (io), F24 I/OG5 <22> (io), F25 I/OG5 <21> (io), F26 I/OG5 <20> (io), G1 I/OG5 <11> (io), G2 I/OG5 <10> (io), G3 I/OG5 <9> (io), G4 I/OG5 <8> (io), G23 I/OG5 <19> (io), G24 I/OG5 <18> (io), G25 I/OG5 <17> (io), G26 I/OG5 <16> (io), H1 I/OG4 <6> (io), H2 I/OG4 <8> (io), H3 I/OG4 <9> (io), H4 I/OG4 <10> (io), H5 I/OG4 <1> (io), H6 I/OG3 <3> (io), H21 I/OG3 <20> (io), H22 I/OG4 <21> (io), H23 I/OG5 <15> (io), H24 I/OG5 <14> (io), H25 I/OG5 <13> (io), H26 I/OG4 <12> (io), J1 I/OG4 <2> (io), J2 I/OG4 <3> (io), J3 I/OG4 <4> (io), J4 I/OG4 <5> (io), J5 I/OG4 <7> (io), J22 I/OG4 <16> (io), J23 I/OG4 <13> (io), J24 I/OG4 <14> (io), J25 I/OG4 <15> (io), J26 I/OG4 <17> (io), K1 I/OG3 <1> (io), K2 I/OG3 <0> (io), K4 I/OG4 <0> (io), K6 I/OG4 <11> (io), K21 I/OG5 <12> (io), K23 I/OG4 <18> (io), K24 I/OG4 <19> (io), K25 I/OG4 <20> (io), K26 I/OG4 <22> (io), L1 I/OG3 <6> (io), L2 I/OG3 <2> (io), L3 I/OG3 <4> (io), L4 I/OG3 <5> (io), L23 I/OG3 <23> (io), L25 I/OG4 <23> (io), L26 I/OG3 <22> (io), M1 I/OG3 <8> (io), M2 I/OG3 <7> (io), M3 I/OG3 <9> (io), M4 I/OG3 <10> (io), M22 I/OG3 <16> (io), M23 I/OG3 <17> (io), M24 I/OG3 <18> (io), M25 I/OG3 <21> (io), M26 I/OG3 <19> (io), N2 I/OG3 <11> (io), N4 I/OG2 <11> (io), N23 I/OG3 <12> (io), N24 I/OG3 <13> (io), N25 I/OG3 <15> (io), N26 I/OG3 <14> (io), P1 I/OG2 <8> (io), P3 I/OG2 <9> (io), P4 I/OG2 <10> (io), P25 I/OG2 <13> (io), P26 I/OG2 <12> (io), R1 I/OG2 <4> (io), R2 I/OG2 <3> (io), R3 I/OG2 <5> (io), R4 I/OG2 <6> (io), R5 I/OG2 <7> (io), R23 I/OG2 <14> (io), R25 I/OG2 <17> (io), R26 I/OG2 <16> (io), T1 I/OG2 <1> (io), T4 I/OG2 <0> (io), T22 I/OG2 <15> (io), T23 I/OG2 <19> (io), T24 I/OG2 <21> (io), T25 I/OG2 <22> (io), T26 I/OG2 <18> (io), U26 I/OG2 <23> (io), W6 I/OG2 <2> (io), W21 I/OG2 <20> (io)
part D pins: A1 NC, A6 NC, A7 NC, A8 NC, A16 NC, A20 NC, A21 NC, A22 NC, AA8 NC, AA9 NC, AA18 NC, AA19 NC, AB1 NC, AB2 NC, AB3 NC, AB4 NC, AB6 NC, AB10 NC, AB20 NC, AB21 NC, AB23 NC, AC1 NC, AC2 NC, AC3 NC, AC6 NC, AC7 NC, AC8 NC, AC18 NC, AC19 NC, AC20 NC, AC23 NC, AC24 NC, AC25 NC, AC26 NC, AD1 NC, AD2 NC, AD3 NC, AD6 NC, AD7 NC, AD8 NC, AD15 NC, AD19 NC, AD20 NC, AD25 NC, AD26 NC, AE1 NC, AE6 NC, AE7 NC, AE8 NC, AE19 NC, AE20 NC, AE21 NC, AE25 NC, AE26 NC, AF6 NC, AF7 NC, AF8 NC, AF19 NC, AF20 NC, AF21 NC, AF25 NC, AF26 NC, B1 NC, B2 NC, B7 NC, B8 NC, B9 NC, B20 NC, B21 NC, C1 NC, C2 NC, C3 NC, C7 NC, C8 NC, C9 NC, C19 NC, C20 NC, C21 NC, C24 NC, C25 NC, C26 NC, D1 NC, D2 NC, D3 NC, D4 NC, D7 NC, D8 NC, D9 NC, D19 NC, D20 NC, D21 NC, D24 NC, D25 NC, D26 NC, E6 NC, E17 NC, E20 NC, E21 NC, E23 NC, E24 NC, E25 NC, E26 NC, F8 NC, F9 NC, F18 NC, F19 NC, G6 NC, G21 NC, Y6 NC, Y21 NC
part E pins: AA5 VCC (power), AA6 GND (power), AA7 VCCIO (power), AA10 VCC (power), AA17 VCC (power), AA20 VCCIO (power), AA21 GND (power), AA22 VCC (power), AB5 GND (power), AB8 VCCIO (power), AB9 VCC (power), AB12 VCC (power), AB13 GND (power), AB14 VCCIO (power), AB15 VCC (power), AB16 GND (power), AB18 VCC (power), AB19 VCCIO (power), AB22 GND (power), E5 GND (power), E8 VCCIO (power), E9 VCC (power), E11 GND (power), E12 VCC (power), E13 VCCIO (power), E14 GND (power), E15 VCC (power), E18 VCC (power), E19 VCCIO (power), E22 GND (power), F5 VCC (power), F6 GND (power), F7 VCCIO (power), F10 VCC (power), F17 VCC (power), F20 VCCIO (power), F21 GND (power), F22 VCC (power), G5 VCC (power), G22 VCC (power), J6 VCCIO (power), J21 VCCIO (power), K3 VCCIO (power), K5 VCC (power), K22 VCC (power), L11 GND (power), L12 GND (power), L13 GND (power), L14 GND (power), L15 GND (power), L16 GND (power), L22 VCC (power), L24 VCCIO (power), M5 VCC (power), M11 GND (power), M12 GND (power), M13 GND (power), M14 GND (power), M15 GND (power), M16 GND (power), N1 VCCIO (power), N11 GND (power), N12 GND (power), N13 GND (power), N14 GND (power), N15 GND (power), N16 GND (power), N22 VCC (power), P5 VCC (power), P11 GND (power), P12 GND (power), P13 GND (power), P14 GND (power), P15 GND (power), P16 GND (power), P24 VCCIO (power), R11 GND (power), R12 GND (power), R13 GND (power), R14 GND (power), R15 GND (power), R16 GND (power), R22 VCC (power), T3 VCCIO (power), T5 VCC (power), T11 GND (power), T12 GND (power), T13 GND (power), T14 GND (power), T15 GND (power), T16 GND (power), U5 VCC (power), U22 VCC (power), U25 VCCIO (power), V6 VCCIO (power), Y5 VCC (power), Y22 VCC (power), Y23 VCCIO (power)

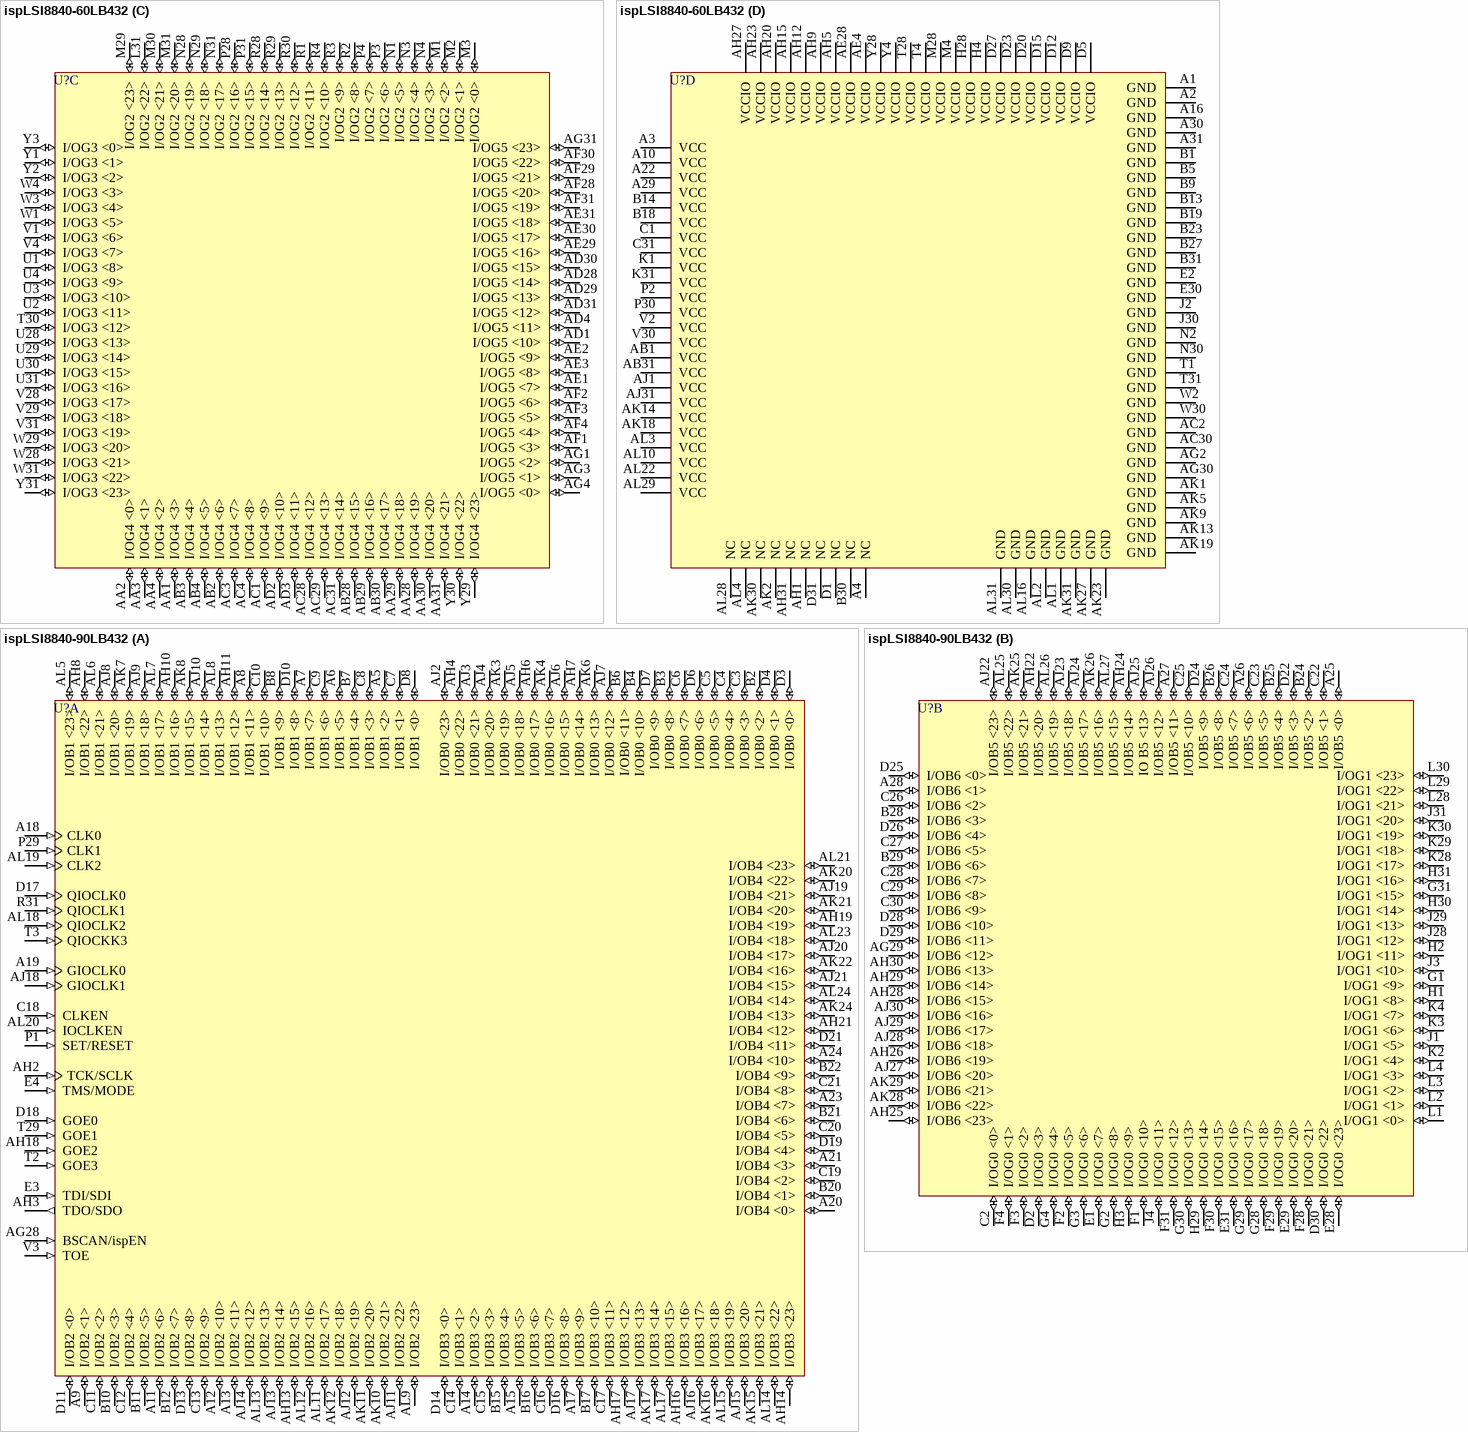
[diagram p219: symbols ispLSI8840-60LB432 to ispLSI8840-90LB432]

## ispLSI8840-60LB432
designator U?
In-System Programmable SuperBIG High Density PLD
footprint SBGA432 (BGA, 432-Leads, Body 40x40mm, Pitch 1.27mm)
3D model 8840-SBGA432 (432-Ball Super Ball Grid Array (SBGA432))
part A pins: A5 I/OB1 <2> (io), A6 I/OB1 <5> (io), A7 I/OB1 <7> (io), A8 I/OB1 <11> (io), A9 I/OB2 <1> (io), A11 I/OB2 <6> (io), A12 I/OB2 <10> (io), A13 I/OB2 <11> (io), A14 I/OB3 <2> (io), A15 I/OB3 <5> (io), A17 I/OB3 <9> (io), A18 CLK0 (in), A19 GIOCLK0 (in), A20 I/OB4 <0> (io), A21 I/OB4 <3> (io), A23 I/OB4 <7> (io), A24 I/OB4 <10> (io), AG28 BSCAN/ispEN (in), AH2 TCK/SCLK (in), AH3 TDO/SDO (out), AH4 I/OB0 <22> (io), AH6 I/OB0 <17> (io), AH7 I/OB0 <14> (io), AH8 I/OB1 <22> (io), AH10 I/OB1 <16> (io), AH11 I/OB1 <12> (io), AH13 I/OB2 <15> (io), AH14 I/OB3 <23> (io), AH16 I/OB3 <16> (io), AH17 I/OB3 <12> (io), AH18 GOE2 (in), AH19 I/OB4 <19> (io), AH21 I/OB4 <12> (io), AJ2 I/OB0 <23> (io), AJ3 I/OB0 <21> (io), AJ4 I/OB0 <20> (io), AJ5 I/OB0 <18> (io), AJ6 I/OB0 <15> (io), AJ7 I/OB0 <12> (io), AJ8 I/OB1 <20> (io), AJ9 I/OB1 <18> (io), AJ10 I/OB1 <14> (io), AJ11 I/OB2 <22> (io), AJ12 I/OB2 <19> (io), AJ13 I/OB2 <14> (io), AJ14 I/OB2 <12> (io), AJ15 I/OB3 <20> (io), AJ16 I/OB3 <17> (io), AJ17 I/OB3 <13> (io), AJ18 GIOCLK1 (in), AJ19 I/OB4 <21> (io), AJ20 I/OB4 <17> (io), AJ21 I/OB4 <15> (io), AK3 I/OB0 <19> (io), AK4 I/OB0 <16> (io), AK6 I/OB0 <13> (io), AK7 I/OB1 <19> (io), AK8 I/OB1 <15> (io), AK10 I/OB2 <21> (io), AK11 I/OB2 <20> (io), AK12 I/OB2 <18> (io), AK15 I/OB3 <21> (io), AK16 I/OB3 <18> (io), AK17 I/OB3 <14> (io), AK20 I/OB4 <22> (io), AK21 I/OB4 <20> (io), AK22 I/OB4 <16> (io), AK24 I/OB4 <13> (io), AL5 I/OB1 <23> (io), AL6 I/OB1 <21> (io), AL7 I/OB1 <17> (io), AL8 I/OB1 <13> (io), AL9 I/OB2 <23> (io), AL11 I/OB2 <17> (io), AL12 I/OB2 <16> (io), AL13 I/OB2 <13> (io), AL14 I/OB3 <22> (io), AL15 I/OB3 <19> (io), AL17 I/OB3 <15> (io), AL18 QIOCLK2 (in), AL19 CLK2 (in), AL20 IOCLKEN (in), AL21 I/OB4 <23> (io), AL23 I/OB4 <18> (io), AL24 I/OB4 <14> (io), B2 I/OB0 <2> (io), B3 I/OB0 <8> (io), B4 I/OB0 <10> (io), B6 I/OB0 <11> (io), B7 I/OB1 <4> (io), B8 I/OB1 <9> (io), B10 I/OB2 <3> (io), B11 I/OB2 <5> (io), B12 I/OB2 <7> (io), B15 I/OB3 <4> (io), B16 I/OB3 <6> (io), B17 I/OB3 <10> (io), B20 I/OB4 <1> (io), B21 I/OB4 <6> (io), B22 I/OB4 <9> (io), C3 I/OB0 <3> (io), C4 I/OB0 <4> (io), C5 I/OB0 <5> (io), C6 I/OB0 <7> (io), C7 I/OB1 <1> (io), C8 I/OB1 <3> (io), C9 I/OB1 <6> (io), C10 I/OB1 <10> (io), C11 I/OB2 <2> (io), C12 I/OB2 <4> (io), C13 I/OB2 <9> (io), C14 I/OB3 <1> (io), C15 I/OB3 <3> (io), C16 I/OB3 <7> (io), C17 I/OB3 <11> (io), C18 CLKEN (in), C19 I/OB4 <2> (io), C20 I/OB4 <5> (io), C21 I/OB4 <8> (io), D3 I/OB0 <0> (io), D4 I/OB0 <1> (io), D6 I/OB0 <6> (io), D7 I/OB0 <9> (io), D8 I/OB1 <0> (io), D10 I/OB1 <8> (io), D11 I/OB2 <0> (io), D13 I/OB2 <8> (io), D14 I/OB3 <0> (io), D16 I/OB3 <8> (io), D17 QIOCLK0 (in), D18 GOE0 (in), D19 I/OB4 <4> (io), D21 I/OB4 <11> (io), E3 TDI/SDI (in), E4 TMS/MODE (in), P1 SET/RESET (in), P29 CLK1 (in), R31 QIOCLK1 (in), T2 GOE3 (in), T3 QIOCKK3 (in), T29 GOE1 (in), V3 TOE (in)
part B pins: A25 I/OB5 <0> (io), A26 I/OB5 <6> (io), A27 I/OB5 <11> (io), A28 I/OB6 <1> (io), AG29 I/OB6 <12> (io), AH22 I/OB5 <20> (io), AH24 I/OB5 <14> (io), AH25 I/OB6 <23> (io), AH26 I/OB6 <19> (io), AH28 I/OB6 <15> (io), AH29 I/OB6 <14> (io), AH30 I/OB6 <13> (io), AJ22 I/OB5 <23> (io), AJ23 I/OB5 <18> (io), AJ24 I/OB5 <17> (io), AJ25 IO B5 <13> (io), AJ26 I/OB5 <12> (io), AJ27 I/OB6 <20> (io), AJ28 I/OB6 <18> (io), AJ29 I/OB6 <17> (io), AJ30 I/OB6 <16> (io), AK25 I/OB5 <21> (io), AK26 I/OB5 <16> (io), AK28 I/OB6 <22> (io), AK29 I/OB6 <21> (io), AL25 I/OB5 <22> (io), AL26 I/OB5 <19> (io), AL27 I/OB5 <15> (io), B24 I/OB5 <2> (io), B25 I/OB5 <4> (io), B26 I/OB5 <8> (io), B28 I/OB6 <3> (io), B29 I/OB6 <6> (io), C2 I/OG0 <0> (io), C22 I/OB5 <1> (io), C23 I/OB5 <5> (io), C24 I/OB5 <7> (io), C25 I/OB5 <10> (io), C26 I/OB6 <2> (io), C27 I/OB6 <5> (io), C28 I/OB6 <7> (io), C29 I/OB6 <8> (io), C30 I/OB6 <9> (io), D2 I/OG0 <3> (io), D22 I/OB5 <3> (io), D24 I/OB5 <9> (io), D25 I/OB6 <0> (io), D26 I/OB6 <4> (io), D28 I/OB6 <10> (io), D29 I/OB6 <11> (io), D30 I/OG0 <22> (io), E1 I/OG0 <7> (io), E28 I/OG0 <23> (io), E29 I/OG0 <20> (io), E31 I/OG0 <16> (io), F1 I/OG0 <10> (io), F2 I/OG0 <5> (io), F3 I/OG0 <2> (io), F4 I/OG0 <1> (io), F28 I/OG0 <21> (io), F29 I/OG0 <19> (io), F30 I/OG0 <15> (io), F31 I/OG0 <12> (io), G1 I/OG1 <9> (io), G2 I/OG0 <8> (io), G3 I/OG0 <6> (io), G4 I/OG0 <4> (io), G28 I/OG0 <18> (io), G29 I/OG0 <17> (io), G30 I/OG0 <13> (io), G31 I/OG1 <15> (io), H1 I/OG1 <8> (io), H2 I/OG1 <11> (io), H3 I/OG0 <9> (io), H29 I/OG0 <14> (io), H30 I/OG1 <14> (io), H31 I/OG1 <16> (io), J1 I/OG1 <5> (io), J3 I/OG1 <10> (io), J4 I/OG0 <11> (io), J28 I/OG1 <12> (io), J29 I/OG1 <13> (io), J31 I/OG1 <20> (io), K2 I/OG1 <4> (io), K3 I/OG1 <6> (io), K4 I/OG1 <7> (io), K28 I/OG1 <17> (io), K29 I/OG1 <18> (io), K30 I/OG1 <19> (io), L1 I/OG1 <0> (io), L2 I/OG1 <1> (io), L3 I/OG1 <2> (io), L4 I/OG1 <3> (io), L28 I/OG1 <21> (io), L29 I/OG1 <22> (io), L30 I/OG1 <23> (io)
part C pins: AA1 I/OG4 <3> (io), AA2 I/OG4 <0> (io), AA3 I/OG4 <1> (io), AA4 I/OG4 <2> (io), AA28 I/OG4 <19> (io), AA29 I/OG4 <18> (io), AA30 I/OG4 <20> (io), AA31 I/OG4 <21> (io), AB2 I/OG4 <6> (io), AB3 I/OG4 <4> (io), AB4 I/OG4 <5> (io), AB28 I/OG4 <15> (io), AB29 I/OG4 <16> (io), AB30 I/OG4 <17> (io), AC1 I/OG4 <9> (io), AC3 I/OG4 <7> (io), AC4 I/OG4 <8> (io), AC28 I/OG4 <12> (io), AC29 I/OG4 <13> (io), AC31 I/OG4 <14> (io), AD1 I/OG5 <10> (io), AD2 I/OG4 <10> (io), AD3 I/OG4 <11> (io), AD4 I/OG5 <11> (io), AD28 I/OG5 <14> (io), AD29 I/OG5 <13> (io), AD30 I/OG5 <15> (io), AD31 I/OG5 <12> (io), AE1 I/OG5 <7> (io), AE2 I/OG5 <9> (io), AE3 I/OG5 <8> (io), AE29 I/OG5 <16> (io), AE30 I/OG5 <17> (io), AE31 I/OG5 <18> (io), AF1 I/OG5 <3> (io), AF2 I/OG5 <6> (io), AF3 I/OG5 <5> (io), AF4 I/OG5 <4> (io), AF28 I/OG5 <20> (io), AF29 I/OG5 <21> (io), AF30 I/OG5 <22> (io), AF31 I/OG5 <19> (io), AG1 I/OG5 <2> (io), AG3 I/OG5 <1> (io), AG4 I/OG5 <0> (io), AG31 I/OG5 <23> (io), L31 I/OG2 <22> (io), M1 I/OG2 <2> (io), M2 I/OG2 <1> (io), M3 I/OG2 <0> (io), M29 I/OG2 <23> (io), M30 I/OG2 <21> (io), M31 I/OG2 <20> (io), N1 I/OG2 <5> (io), N3 I/OG2 <4> (io), N4 I/OG2 <3> (io), N28 I/OG2 <19> (io), N29 I/OG2 <18> (io), N31 I/OG2 <17> (io), P3 I/OG2 <6> (io), P4 I/OG2 <7> (io), P28 I/OG2 <16> (io), P31 I/OG2 <15> (io), R1 I/OG2 <11> (io), R2 I/OG2 <8> (io), R3 I/OG2 <9> (io), R4 I/OG2 <10> (io), R28 I/OG2 <14> (io), R29 I/OG2 <13> (io), R30 I/OG2 <12> (io), T30 I/OG3 <12> (io), U1 I/OG3 <8> (io), U2 I/OG3 <11> (io), U3 I/OG3 <10> (io), U4 I/OG3 <9> (io), U28 I/OG3 <13> (io), U29 I/OG3 <14> (io), U30 I/OG3 <15> (io), U31 I/OG3 <16> (io), V1 I/OG3 <6> (io), V4 I/OG3 <7> (io), V28 I/OG3 <17> (io), V29 I/OG3 <18> (io), V31 I/OG3 <19> (io), W1 I/OG3 <5> (io), W3 I/OG3 <4> (io), W4 I/OG3 <3> (io), W28 I/OG3 <21> (io), W29 I/OG3 <20> (io), W31 I/OG3 <22> (io), Y1 I/OG3 <1> (io), Y2 I/OG3 <2> (io), Y3 I/OG3 <0> (io), Y29 I/OG4 <23> (io), Y30 I/OG4 <22> (io), Y31 I/OG3 <23> (io)
part D pins: A1 GND (power), A2 GND (power), A3 VCC (power), A4 NC, A10 VCC (power), A16 GND (power), A22 VCC (power), A29 VCC (power), A30 GND (power), A31 GND (power), AB1 VCC (power), AB31 VCC (power), AC2 GND (power), AC30 GND (power), AE4 VCCIO (power), AE28 VCCIO (power), AG2 GND (power), AG30 GND (power), AH1 NC, AH5 VCCIO (power), AH9 VCCIO (power), AH12 VCCIO (power), AH15 VCCIO (power), AH20 VCCIO (power), AH23 VCCIO (power), AH27 VCCIO (power), AH31 NC, AJ1 VCC (power), AJ31 VCC (power), AK1 GND (power), AK2 NC, AK5 GND (power), AK9 GND (power), AK13 GND (power), AK14 VCC (power), AK18 VCC (power), AK19 GND (power), AK23 GND (power), AK27 GND (power), AK30 NC, AK31 GND (power), AL1 GND (power), AL2 GND (power), AL3 VCC (power), AL4 NC, AL10 VCC (power), AL16 GND (power), AL22 VCC (power), AL28 NC, AL29 VCC (power), AL30 GND (power), AL31 GND (power), B1 GND (power), B5 GND (power), B9 GND (power), B13 GND (power), B14 VCC (power), B18 VCC (power), B19 GND (power), B23 GND (power), B27 GND (power), B30 NC, B31 GND (power), C1 VCC (power), C31 VCC (power), D1 NC, D5 VCCIO (power), D9 VCCIO (power), D12 VCCIO (power), D15 VCCIO (power), D20 VCCIO (power), D23 VCCIO (power), D27 VCCIO (power), D31 NC, E2 GND (power), E30 GND (power), H4 VCCIO (power), H28 VCCIO (power), J2 GND (power), J30 GND (power), K1 VCC (power), K31 VCC (power), M4 VCCIO (power), M28 VCCIO (power), N2 GND (power), N30 GND (power), P2 VCC (power), P30 VCC (power), T1 GND (power), T4 VCCIO (power), T28 VCCIO (power), T31 GND (power), V2 VCC (power), V30 VCC (power), W2 GND (power), W30 GND (power), Y4 VCCIO (power), Y28 VCCIO (power)

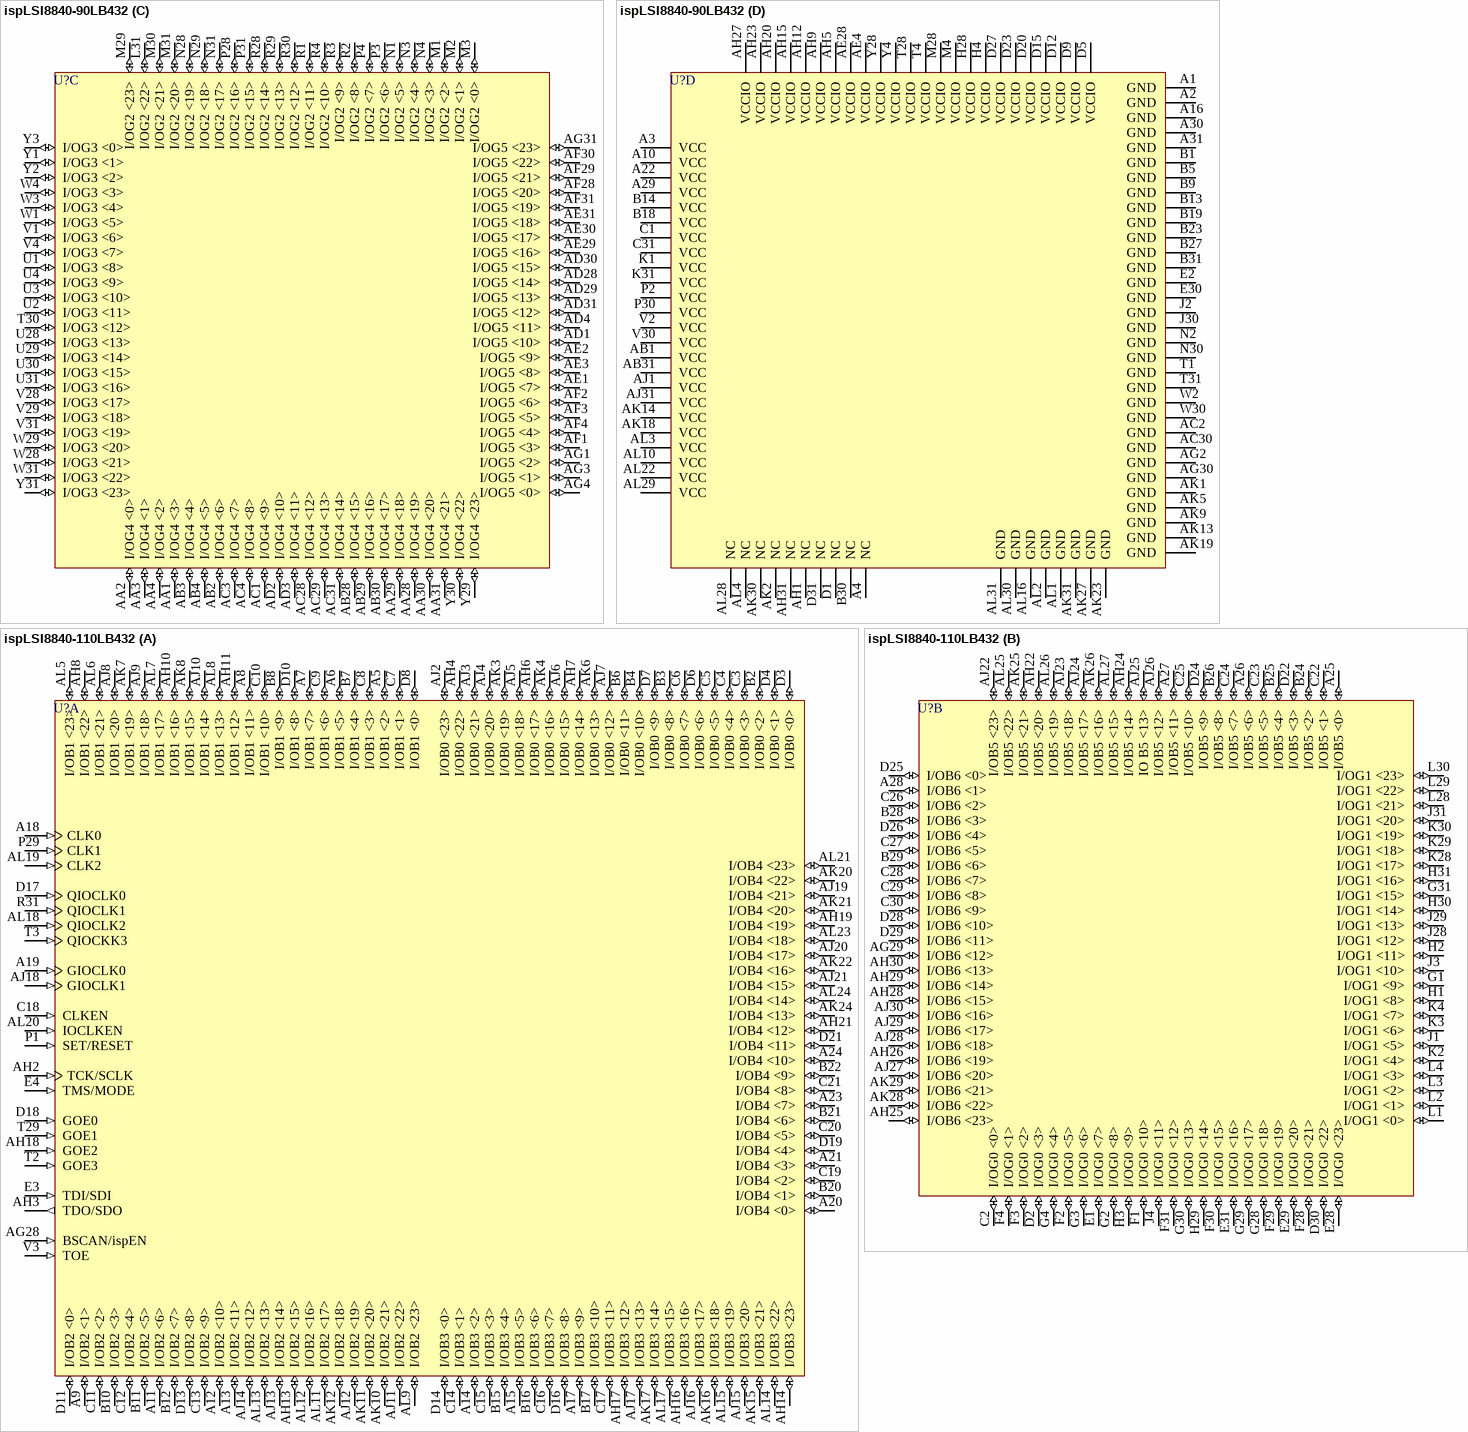
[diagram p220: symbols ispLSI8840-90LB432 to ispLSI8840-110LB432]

## ispLSI8840-90LB432
designator U?
In-System Programmable SuperBIG High Density PLD
footprint SBGA432 (BGA, 432-Leads, Body 40x40mm, Pitch 1.27mm)
3D model 8840-SBGA432 (432-Ball Super Ball Grid Array (SBGA432))
part A pins: A5 I/OB1 <2> (io), A6 I/OB1 <5> (io), A7 I/OB1 <7> (io), A8 I/OB1 <11> (io), A9 I/OB2 <1> (io), A11 I/OB2 <6> (io), A12 I/OB2 <10> (io), A13 I/OB2 <11> (io), A14 I/OB3 <2> (io), A15 I/OB3 <5> (io), A17 I/OB3 <9> (io), A18 CLK0 (in), A19 GIOCLK0 (in), A20 I/OB4 <0> (io), A21 I/OB4 <3> (io), A23 I/OB4 <7> (io), A24 I/OB4 <10> (io), AG28 BSCAN/ispEN (in), AH2 TCK/SCLK (in), AH3 TDO/SDO (out), AH4 I/OB0 <22> (io), AH6 I/OB0 <17> (io), AH7 I/OB0 <14> (io), AH8 I/OB1 <22> (io), AH10 I/OB1 <16> (io), AH11 I/OB1 <12> (io), AH13 I/OB2 <15> (io), AH14 I/OB3 <23> (io), AH16 I/OB3 <16> (io), AH17 I/OB3 <12> (io), AH18 GOE2 (in), AH19 I/OB4 <19> (io), AH21 I/OB4 <12> (io), AJ2 I/OB0 <23> (io), AJ3 I/OB0 <21> (io), AJ4 I/OB0 <20> (io), AJ5 I/OB0 <18> (io), AJ6 I/OB0 <15> (io), AJ7 I/OB0 <12> (io), AJ8 I/OB1 <20> (io), AJ9 I/OB1 <18> (io), AJ10 I/OB1 <14> (io), AJ11 I/OB2 <22> (io), AJ12 I/OB2 <19> (io), AJ13 I/OB2 <14> (io), AJ14 I/OB2 <12> (io), AJ15 I/OB3 <20> (io), AJ16 I/OB3 <17> (io), AJ17 I/OB3 <13> (io), AJ18 GIOCLK1 (in), AJ19 I/OB4 <21> (io), AJ20 I/OB4 <17> (io), AJ21 I/OB4 <15> (io), AK3 I/OB0 <19> (io), AK4 I/OB0 <16> (io), AK6 I/OB0 <13> (io), AK7 I/OB1 <19> (io), AK8 I/OB1 <15> (io), AK10 I/OB2 <21> (io), AK11 I/OB2 <20> (io), AK12 I/OB2 <18> (io), AK15 I/OB3 <21> (io), AK16 I/OB3 <18> (io), AK17 I/OB3 <14> (io), AK20 I/OB4 <22> (io), AK21 I/OB4 <20> (io), AK22 I/OB4 <16> (io), AK24 I/OB4 <13> (io), AL5 I/OB1 <23> (io), AL6 I/OB1 <21> (io), AL7 I/OB1 <17> (io), AL8 I/OB1 <13> (io), AL9 I/OB2 <23> (io), AL11 I/OB2 <17> (io), AL12 I/OB2 <16> (io), AL13 I/OB2 <13> (io), AL14 I/OB3 <22> (io), AL15 I/OB3 <19> (io), AL17 I/OB3 <15> (io), AL18 QIOCLK2 (in), AL19 CLK2 (in), AL20 IOCLKEN (in), AL21 I/OB4 <23> (io), AL23 I/OB4 <18> (io), AL24 I/OB4 <14> (io), B2 I/OB0 <2> (io), B3 I/OB0 <8> (io), B4 I/OB0 <10> (io), B6 I/OB0 <11> (io), B7 I/OB1 <4> (io), B8 I/OB1 <9> (io), B10 I/OB2 <3> (io), B11 I/OB2 <5> (io), B12 I/OB2 <7> (io), B15 I/OB3 <4> (io), B16 I/OB3 <6> (io), B17 I/OB3 <10> (io), B20 I/OB4 <1> (io), B21 I/OB4 <6> (io), B22 I/OB4 <9> (io), C3 I/OB0 <3> (io), C4 I/OB0 <4> (io), C5 I/OB0 <5> (io), C6 I/OB0 <7> (io), C7 I/OB1 <1> (io), C8 I/OB1 <3> (io), C9 I/OB1 <6> (io), C10 I/OB1 <10> (io), C11 I/OB2 <2> (io), C12 I/OB2 <4> (io), C13 I/OB2 <9> (io), C14 I/OB3 <1> (io), C15 I/OB3 <3> (io), C16 I/OB3 <7> (io), C17 I/OB3 <11> (io), C18 CLKEN (in), C19 I/OB4 <2> (io), C20 I/OB4 <5> (io), C21 I/OB4 <8> (io), D3 I/OB0 <0> (io), D4 I/OB0 <1> (io), D6 I/OB0 <6> (io), D7 I/OB0 <9> (io), D8 I/OB1 <0> (io), D10 I/OB1 <8> (io), D11 I/OB2 <0> (io), D13 I/OB2 <8> (io), D14 I/OB3 <0> (io), D16 I/OB3 <8> (io), D17 QIOCLK0 (in), D18 GOE0 (in), D19 I/OB4 <4> (io), D21 I/OB4 <11> (io), E3 TDI/SDI (in), E4 TMS/MODE (in), P1 SET/RESET (in), P29 CLK1 (in), R31 QIOCLK1 (in), T2 GOE3 (in), T3 QIOCKK3 (in), T29 GOE1 (in), V3 TOE (in)
part B pins: A25 I/OB5 <0> (io), A26 I/OB5 <6> (io), A27 I/OB5 <11> (io), A28 I/OB6 <1> (io), AG29 I/OB6 <12> (io), AH22 I/OB5 <20> (io), AH24 I/OB5 <14> (io), AH25 I/OB6 <23> (io), AH26 I/OB6 <19> (io), AH28 I/OB6 <15> (io), AH29 I/OB6 <14> (io), AH30 I/OB6 <13> (io), AJ22 I/OB5 <23> (io), AJ23 I/OB5 <18> (io), AJ24 I/OB5 <17> (io), AJ25 IO B5 <13> (io), AJ26 I/OB5 <12> (io), AJ27 I/OB6 <20> (io), AJ28 I/OB6 <18> (io), AJ29 I/OB6 <17> (io), AJ30 I/OB6 <16> (io), AK25 I/OB5 <21> (io), AK26 I/OB5 <16> (io), AK28 I/OB6 <22> (io), AK29 I/OB6 <21> (io), AL25 I/OB5 <22> (io), AL26 I/OB5 <19> (io), AL27 I/OB5 <15> (io), B24 I/OB5 <2> (io), B25 I/OB5 <4> (io), B26 I/OB5 <8> (io), B28 I/OB6 <3> (io), B29 I/OB6 <6> (io), C2 I/OG0 <0> (io), C22 I/OB5 <1> (io), C23 I/OB5 <5> (io), C24 I/OB5 <7> (io), C25 I/OB5 <10> (io), C26 I/OB6 <2> (io), C27 I/OB6 <5> (io), C28 I/OB6 <7> (io), C29 I/OB6 <8> (io), C30 I/OB6 <9> (io), D2 I/OG0 <3> (io), D22 I/OB5 <3> (io), D24 I/OB5 <9> (io), D25 I/OB6 <0> (io), D26 I/OB6 <4> (io), D28 I/OB6 <10> (io), D29 I/OB6 <11> (io), D30 I/OG0 <22> (io), E1 I/OG0 <7> (io), E28 I/OG0 <23> (io), E29 I/OG0 <20> (io), E31 I/OG0 <16> (io), F1 I/OG0 <10> (io), F2 I/OG0 <5> (io), F3 I/OG0 <2> (io), F4 I/OG0 <1> (io), F28 I/OG0 <21> (io), F29 I/OG0 <19> (io), F30 I/OG0 <15> (io), F31 I/OG0 <12> (io), G1 I/OG1 <9> (io), G2 I/OG0 <8> (io), G3 I/OG0 <6> (io), G4 I/OG0 <4> (io), G28 I/OG0 <18> (io), G29 I/OG0 <17> (io), G30 I/OG0 <13> (io), G31 I/OG1 <15> (io), H1 I/OG1 <8> (io), H2 I/OG1 <11> (io), H3 I/OG0 <9> (io), H29 I/OG0 <14> (io), H30 I/OG1 <14> (io), H31 I/OG1 <16> (io), J1 I/OG1 <5> (io), J3 I/OG1 <10> (io), J4 I/OG0 <11> (io), J28 I/OG1 <12> (io), J29 I/OG1 <13> (io), J31 I/OG1 <20> (io), K2 I/OG1 <4> (io), K3 I/OG1 <6> (io), K4 I/OG1 <7> (io), K28 I/OG1 <17> (io), K29 I/OG1 <18> (io), K30 I/OG1 <19> (io), L1 I/OG1 <0> (io), L2 I/OG1 <1> (io), L3 I/OG1 <2> (io), L4 I/OG1 <3> (io), L28 I/OG1 <21> (io), L29 I/OG1 <22> (io), L30 I/OG1 <23> (io)
part C pins: AA1 I/OG4 <3> (io), AA2 I/OG4 <0> (io), AA3 I/OG4 <1> (io), AA4 I/OG4 <2> (io), AA28 I/OG4 <19> (io), AA29 I/OG4 <18> (io), AA30 I/OG4 <20> (io), AA31 I/OG4 <21> (io), AB2 I/OG4 <6> (io), AB3 I/OG4 <4> (io), AB4 I/OG4 <5> (io), AB28 I/OG4 <15> (io), AB29 I/OG4 <16> (io), AB30 I/OG4 <17> (io), AC1 I/OG4 <9> (io), AC3 I/OG4 <7> (io), AC4 I/OG4 <8> (io), AC28 I/OG4 <12> (io), AC29 I/OG4 <13> (io), AC31 I/OG4 <14> (io), AD1 I/OG5 <10> (io), AD2 I/OG4 <10> (io), AD3 I/OG4 <11> (io), AD4 I/OG5 <11> (io), AD28 I/OG5 <14> (io), AD29 I/OG5 <13> (io), AD30 I/OG5 <15> (io), AD31 I/OG5 <12> (io), AE1 I/OG5 <7> (io), AE2 I/OG5 <9> (io), AE3 I/OG5 <8> (io), AE29 I/OG5 <16> (io), AE30 I/OG5 <17> (io), AE31 I/OG5 <18> (io), AF1 I/OG5 <3> (io), AF2 I/OG5 <6> (io), AF3 I/OG5 <5> (io), AF4 I/OG5 <4> (io), AF28 I/OG5 <20> (io), AF29 I/OG5 <21> (io), AF30 I/OG5 <22> (io), AF31 I/OG5 <19> (io), AG1 I/OG5 <2> (io), AG3 I/OG5 <1> (io), AG4 I/OG5 <0> (io), AG31 I/OG5 <23> (io), L31 I/OG2 <22> (io), M1 I/OG2 <2> (io), M2 I/OG2 <1> (io), M3 I/OG2 <0> (io), M29 I/OG2 <23> (io), M30 I/OG2 <21> (io), M31 I/OG2 <20> (io), N1 I/OG2 <5> (io), N3 I/OG2 <4> (io), N4 I/OG2 <3> (io), N28 I/OG2 <19> (io), N29 I/OG2 <18> (io), N31 I/OG2 <17> (io), P3 I/OG2 <6> (io), P4 I/OG2 <7> (io), P28 I/OG2 <16> (io), P31 I/OG2 <15> (io), R1 I/OG2 <11> (io), R2 I/OG2 <8> (io), R3 I/OG2 <9> (io), R4 I/OG2 <10> (io), R28 I/OG2 <14> (io), R29 I/OG2 <13> (io), R30 I/OG2 <12> (io), T30 I/OG3 <12> (io), U1 I/OG3 <8> (io), U2 I/OG3 <11> (io), U3 I/OG3 <10> (io), U4 I/OG3 <9> (io), U28 I/OG3 <13> (io), U29 I/OG3 <14> (io), U30 I/OG3 <15> (io), U31 I/OG3 <16> (io), V1 I/OG3 <6> (io), V4 I/OG3 <7> (io), V28 I/OG3 <17> (io), V29 I/OG3 <18> (io), V31 I/OG3 <19> (io), W1 I/OG3 <5> (io), W3 I/OG3 <4> (io), W4 I/OG3 <3> (io), W28 I/OG3 <21> (io), W29 I/OG3 <20> (io), W31 I/OG3 <22> (io), Y1 I/OG3 <1> (io), Y2 I/OG3 <2> (io), Y3 I/OG3 <0> (io), Y29 I/OG4 <23> (io), Y30 I/OG4 <22> (io), Y31 I/OG3 <23> (io)
part D pins: A1 GND (power), A2 GND (power), A3 VCC (power), A4 NC, A10 VCC (power), A16 GND (power), A22 VCC (power), A29 VCC (power), A30 GND (power), A31 GND (power), AB1 VCC (power), AB31 VCC (power), AC2 GND (power), AC30 GND (power), AE4 VCCIO (power), AE28 VCCIO (power), AG2 GND (power), AG30 GND (power), AH1 NC, AH5 VCCIO (power), AH9 VCCIO (power), AH12 VCCIO (power), AH15 VCCIO (power), AH20 VCCIO (power), AH23 VCCIO (power), AH27 VCCIO (power), AH31 NC, AJ1 VCC (power), AJ31 VCC (power), AK1 GND (power), AK2 NC, AK5 GND (power), AK9 GND (power), AK13 GND (power), AK14 VCC (power), AK18 VCC (power), AK19 GND (power), AK23 GND (power), AK27 GND (power), AK30 NC, AK31 GND (power), AL1 GND (power), AL2 GND (power), AL3 VCC (power), AL4 NC, AL10 VCC (power), AL16 GND (power), AL22 VCC (power), AL28 NC, AL29 VCC (power), AL30 GND (power), AL31 GND (power), B1 GND (power), B5 GND (power), B9 GND (power), B13 GND (power), B14 VCC (power), B18 VCC (power), B19 GND (power), B23 GND (power), B27 GND (power), B30 NC, B31 GND (power), C1 VCC (power), C31 VCC (power), D1 NC, D5 VCCIO (power), D9 VCCIO (power), D12 VCCIO (power), D15 VCCIO (power), D20 VCCIO (power), D23 VCCIO (power), D27 VCCIO (power), D31 NC, E2 GND (power), E30 GND (power), H4 VCCIO (power), H28 VCCIO (power), J2 GND (power), J30 GND (power), K1 VCC (power), K31 VCC (power), M4 VCCIO (power), M28 VCCIO (power), N2 GND (power), N30 GND (power), P2 VCC (power), P30 VCC (power), T1 GND (power), T4 VCCIO (power), T28 VCCIO (power), T31 GND (power), V2 VCC (power), V30 VCC (power), W2 GND (power), W30 GND (power), Y4 VCCIO (power), Y28 VCCIO (power)

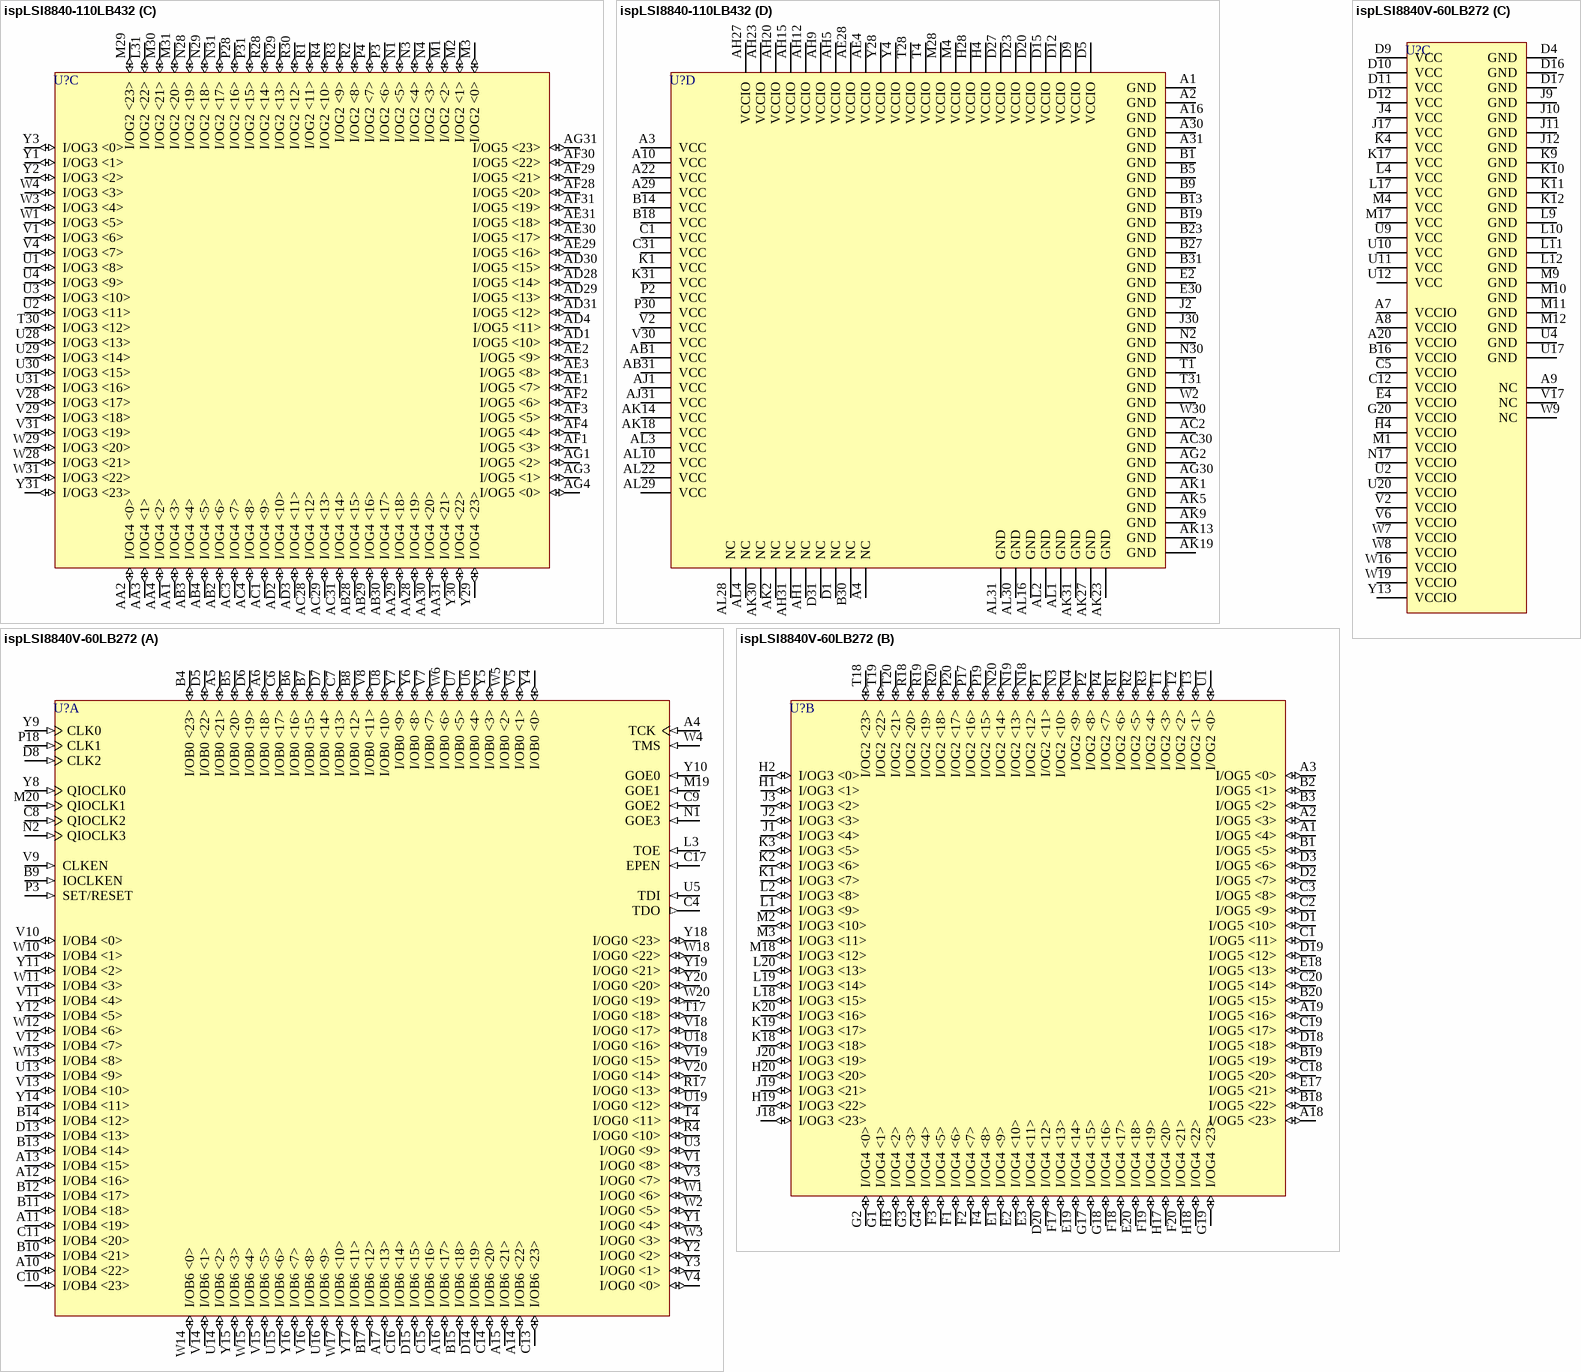
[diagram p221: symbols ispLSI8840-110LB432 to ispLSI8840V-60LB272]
